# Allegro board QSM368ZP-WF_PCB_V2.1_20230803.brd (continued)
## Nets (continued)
100OHM_MIPI_DSI_TX1_D1N_1: D0512.4 J0501.24(MIPI_TDN1) R0571.2
100OHM_MIPI_DSI_TX1_D1P: D0512.1 R0570.1 U1301.34(DSI1_LN1_P)
100OHM_MIPI_DSI_TX1_D1P_1: D0512.3 J0501.23(MIPI_TDP1) R0570.2
100OHM_MIPI_DSI_TX1_D2N: D0511.2 R0569.1 U1301.28(DSI1_LN2_N)
100OHM_MIPI_DSI_TX1_D2N_1: D0511.4 J0501.21(MIPI_TDN2) R0569.2
100OHM_MIPI_DSI_TX1_D2P: D0511.1 R0568.1 U1301.24(DSI1_LN2_P)
100OHM_MIPI_DSI_TX1_D2P_1: D0511.3 J0501.20(MIPI_TDP2) R0568.2
100OHM_MIPI_DSI_TX1_D3N: D0514.2 R0567.1 U1301.23(DSI1_LN3_N)
100OHM_MIPI_DSI_TX1_D3N_1: D0514.4 J0501.18(MIPI_TDN3) R0567.2
100OHM_MIPI_DSI_TX1_D3P: D0514.1 R0566.1 U1301.19(DSI1_LN3_P)
100OHM_MIPI_DSI_TX1_D3P_1: D0514.3 J0501.17(MIPI_TDP3) R0566.2
CAM0_AVDD: B0201.2 J0201.16
CAM0_DOVDD_1V8: B0205.2 J0201.17
CAM0_PDN_L_GPIO3_D5: J0201.24 U1301.316(CAM0_PWDN)
CAM0_RST_L_GPIO3_D4: J0201.14 U1301.317(CAM0_RST)
CAM1_AVDD: B0204.2 J0202.16
CAM1_DOVDD_1V8: B0206.2 J0202.17
CAM1_MCLK: R0226.1 U1301.75(CAM1_MCLK)
CAM1_PDN_L_GPIO3_D3: J0202.24 U1301.313(CAM1_PWDN)
CAM1_RST_L_GPIO3_D2: J0202.14 U1301.314(CAM1_RST)
CAM_DOVDD_1V8: B0205.1 B0206.1 C0209.2 C0299.1 R0207.2 R0208.2 R0212.2 R0221.2 R0222.2 U0205.5(OUT)
CEC_HDMI: D0404.3(D) D0408.1 J0401.13(CEC) R0416.1
CMA0_MCLK: J0201.25 U1301.279(CAM0_MCLK)
DBG_RXD: D1256.2 J1201.23 U1301.378(DBG_RXD)
DBG_TXD: D1255.2 J1201.21 U1301.374(DBG_TXD)
DC12V: C0102.2 C0103.2 C0108.2 C0110.2 C0112.2 C0115.2 C0116.2 C0118.2 C0121.2 C0122.2 C0127.2 C0128.2 C0516.2 C0520.2 C0614.2 C0622.2 C0624.2 C0704.2 C0709.2 C0717.2 C1003.2 C1013.2 C1018.2 C1055.2 C1056.2 D0101.1 F0101.2 Q0502.2(S) R0104.2 R0106.2 R0113.2 R0116.1 R0117.2 R0503.1 R0509.1 R0620.2 R0723.2 TP0102.1 U0101.1(IN) U0103.1(IN) U0104.1(IN) U0604.1(IN) U0701.1(IN) U1001.16(PVCC)
EDP_BL_EN: D0505.3(C) J0502.10 R0522.1
EDP_DET: R0516.2 R0527.2 U1301.70(EDP_DET)
EDP_HPD: J0502.11 R0527.1
EDP_PWM: D0501.3(C) J0502.8 R0506.1
EDP_VDDIN: C0518.1 C0523.1 J0502.1 J0502.2 J0502.3 Q0501.3(D) R0506.2 R0522.2 R0525.2
EDP_VLED: C0506.2 C0522.2 J0502.28 Q0502.3(D) R0509.2
ETH1_REFCLKO_25M_M1: R0925.2 U1301.288(RGMII1_REFCLKOUT)
ETH_3V3_A: B0901.2 C0902.2 C0917.2 R0915.2 R0954.2
EXT_EN: R0166.2 R0526.2 R0644.2 U1301.217(EXT_EN)
FSPI_CS0N/FLASH_CS0N: R1125.2 U1301.281(GPIO1_D3)
FSPI_D0/FLASH_RDY: D0505.1(B) U1301.267(GPIO1_D1)
GMAC1_MDC_M1: R0931.2 U1301.290(RGMII1_MDC)
GMAC1_MDIO_M1: R0949.2 U1301.286(RGMII1_MDIO)
GPIO1_D4: R0709.1 R0721.1 U1301.277(GPIO1_D4)
GPIO3_A4: D0703.1(B) J1201.10 U1301.352(GPIO3_A4)
GPIO3_A7: J1201.12 U1301.347(GPIO3_A7)
GPIO3_D0: D0701.1(B) U1301.318(GPIO3_D0)
GPIO3_D1: D0503.1(B) D0507.1(B) U1301.319(GPIO3_D1)
GPIO4_B2: D0902.3(C) R0935.1 R0941.2 U1301.291(GPIO4_B2)
GPIO4_C2: R0726.1 U1301.376(I2S3_MCLK)
HDMI14_TX_PWREN_H_GPIO0_D5: Q0402.1(B) U1301.80(GPIO0_D5)
HDMI_5V: C0413.2 D0403.1 J0401.18(VCC5V) R0408.2
HDMI_TX_HPD_PORT: D0410.1 J0401.19(DETECT) R0401.1 R0425.1
HDMI_TX_HPDIN: R0401.2 U1301.379(HDMI_DET)
HDMITX_CEC_M0: D0404.2(S) R0428.1 U1301.382(HDMI_CEC)
HDMITX_SCL: R0405.1 U0413.2(S) U1301.387(HDMI_I2C_SCL)
HDMITX_SCL_M: D0407.1 J0401.15(SCL) R0426.1 U0413.3(D)
HDMITX_SDA: R0417.1 U0405.2(S) U1301.385(HDMI_I2C_SDA)
HDMITX_SDA_M: D0406.1 J0401.16(SDA) R0420.1 U0405.3(D)
HP_SNS: R1018.1 U1301.101(HPH_GND)
HPL_OUT: C1017.1 R1004.2 R1023.1 U1301.100(HPH_L)
HPR_OUT: C1016.1 R1010.1 R1024.2 U1301.102(HPH_R)
I2C1_SCL_TP: D0504.2 J0503.2(SCL) J1201.17 R0517.1 U1301.45(TP_I2C1_SCL)
I2C1_SDA_TP: D0509.2 J0503.1(SDA) J1201.19 R0508.1 U1301.40(TP_I2C1_SDA)
I2C2_SCL_M1: J0201.13 R0207.1 U1301.287(I2C2_SCL)
I2C2_SDA_M1: J0201.12 R0221.1 U1301.284(I2C2_SDA)
I2C3_SCL_M0: J0202.13 J1201.13 R0208.1 U1301.273(I2C3_SCL)
I2C3_SDA_M0: J0202.12 J1201.11 R0222.1 U1301.268(I2C3_SDA)
I2C4_SCL_M1: R0430.2 R1206.1 U0410.2(S) U1204.2(SCL) U1301.159(I2C4_SCL)
I2C4_SDA_M1: R0424.2 R1203.1 U0407.2(S) U1204.3(SDA) U1301.155(I2C4_SDA)
I2S3_LRCKM1: R0714.1 U1301.388(I2S3_LRCK)
I2S3_SCLKM1: R0724.1 U1301.386(I2S3_SCLK)
I2S3_SDIM1: R0703.1 U1301.383(I2S3_DIN)
I2S3_SDOM1: R0710.1 U1301.380(I2S3_DOUT)
INTB_A: D0902.1(B) R0935.2 R0953.2 U0902.31(INT_N/PME_N)
LAN0_D2_REC1_A: R0911.2 U0901.24
LAN0_D2_REC2_A: R0918.2 U0901.21
LAN0_D7_REC1_A: R0924.2 U0901.15
LAN0_D7_REC2_A: R0943.2 U0901.18
LCD0_BL_PWM4: R0422.2 U0409.5(CTRL) U1301.55(PWM4)
LCD1_BL_PWM5: R0512.2 U0504.5(CTRL) U1301.25(GPIO0_C4)
LCD_RST_L_GPIO3_C7: J0501.6(RESET) U1301.322(LCD1_RST)
LCDC_D0: R0203.2 U0202.3(EN) U1301.366(PCIE1_CLKREQ_N)
LCDC_D1: R0504.1 R0507.2 U0502.3(EN) U1301.367(PCIE1_WAKE_N)
LCDC_D9: R0204.2 U0204.5(EN) U1301.359(GPIO3_A2)
LCDC_D10: R0223.2 U0203.3(EN) U1301.354(GPIO3_A3)
LCDC_D12: R0228.1 U0205.3(EN) U1301.351(GPIO3_A5)
LCDC_D13: C1024.2 R1014.1 R1017.1 U1301.346(GPIO3_A6)
LCDC_D15: D0905.1(B) R0948.2 U1301.348(GPIO3_B0)
LCDC_D19: R1015.2 R1022.1 U1001.9(CTRL) U1301.342(GPIO3_B4)
LCDC_D21: Q0403.1(B) R0406.2 U1301.337(GPIO3_B6)
LCDC_HSYNC: R0319.1 U1301.333(PCIE1_RST_N)
LCM_LED+: J0501.1(LEDA) R0523.1
LCM_LED-: J0501.3(LEDK) R0530.2 U0504.1(FB)
LCMIO_1V8: C0519.2 J0501.13(VIO18) R0511.2 R0513.1
LED0/PHYAD0_A: R0929.1 R0956.2 U0902.32(LED0/CFG_EXT)
LED1/CFG_LDO0_A: R0901.1 R0907.2 R0933.1 R0939.1 U0902.33(LED1/CFG_LDO0)
LED2/CFG_LDO1_A: R0904.2 R0914.1 R0930.1 R0951.1 U0902.34(LED2/CFG_LDO1)
LVDS_CTP28: B0501.2 C0403.1 J0402.5 R0404.2 R0414.2 R0415.2 R0429.2
LVDS_LEDA: J0403.39 J0403.40 R0402.1
LVDS_LEDK: J0403.31 J0403.32 R0413.2 U0409.1(FB)
LVDS_RESET: C0404.1 J0403.5 Q0403.3(C) R0406.1 R0421.1
LVDS_TP_INT: J0402.3 Q0405.3(D) R0404.1 R0409.1
LVDS_TP_RST: C0406.1 J0402.6 Q0404.3(C) R0418.1 R0429.1
LVDS_TP_SCL: J0402.1 R0414.1 R0430.1 U0410.3(D)
LVDS_TP_SDA: J0402.2 R0415.1 R0424.1 U0407.3(D)
LVDS_VDD3V3: C0407.1 J0403.2 J0403.3 Q0401.3(D) R0421.2 R0427.1
MIC1_INN: R1099.2 U1301.97(MIC_M)
MIC1_INP: C1010.2 R1003.2 U1301.98(MIC_P)
MINI-PCIE-C_DTR: R0709.2 R0715.2
MINI-PCIE-C_RESET: R0706.1 R0711.2
MINI-PCIE-C_RXD: R0701.1 R0702.2
MINI-PCIE-C_TXD: R0707.2 R0732.1
MINI-PCIE-C_VDD_EXT: R0719.1 R0866.1
MINI-PCIE_DTR: R0704.1 R0733.2
MINI-PCIE_LED_WWAN#: D0706.1 J0701.42
MINI-PCIE_RXD: J0701.11 R0719.2 R0731.2
MINI-PCIE_TXD: J0701.13 R0729.2
MINI-PCIE_W_DISABLE#: C0701.2 D0701.3(C) J0701.20
MINI-PCIE_W_RESET#: J0701.22 R0716.2
MIPI_CTP28: B0502.2 C0533.1 J0503.6(VDD)
MODULE_4G_3V5: C0703.1 C0705.1 C0707.2 C0708.2 C0710.1 C0711.2 C0712.2 C0713.2 C0715.2 J0701.2 J0701.39 J0701.41 J0701.52 L0701.2 R0708.1 R0717.2 R0728.2 R0730.1 U0702.14(VCCB)
PDM_CLK1_M0_ADC: J1201.14 U1301.258(PDM_CLK1)
PDM_SDI1_M0_ADC: J1201.16 Q0405.2(S) R0403.1 R0409.2 U1301.253(PDM_DIN1)
PDM_SDI2_M0_ADC: J1201.18 Q0404.1(B) R0418.2 U1301.248(PDM_DIN2)
PDM_SDI3_M0_ADC: J1201.20 U1301.243(PDM_DIN3)
PHY_CLK125_A: R0934.1 U0902.35(CLKOUT)
PHYRSTB_A: C0903.1 D0905.3(C) R0942.2 R0948.1 U0902.12(RESET_N)
REGOUT_A: L0901.1 R0988.2 U0902.30(REG_O/LDO_O/NC)
RS232_RXD: J1201.4 U1103.7(T_OUT1)
RS232_TXD: J1201.2 U1103.8(R_IN1)
RS485_A: D1106.1 J1201.8 R1113.2 R1123.2 U1101.6(A)
RS485_B: D1104.1 J1201.6 R1123.1 R1129.2 U1101.7(B)
RTCIC_32KOUT: R1207.1 U1204.4(FOUT)
RTCIC_INT_L_GPIO0_D3: R1204.1 U1204.6(/IRQ) U1301.125(GPIO0_D3)
SARADC_VIN4: J1201.3 U1301.233(ADC4)
SARADC_VIN5: J1201.9 U1301.228(ADC5)
SARADC_VIN6: J1201.5 U1301.223(ADC6)
SARADC_VIN7: J1201.7 R0528.2 U1301.213(ADC7)
SDMMC0_DET_L: R0807.1 R0809.2 U1301.261(SD_DET)
SDMMC0_DET_L1: D0808.1 J0801.CD(CARD DETECION) R0807.2
SG368Z_PWRKEY: R1208.1 TP1203.1 U1301.226(PWRKEY)
SPK_OUT_LN: B1003.1 C1006.2 J1001.4
SPK_OUT_LP: B1005.1 C1009.1 J1001.3
SPK_OUT_RN: B1004.1 C1025.1 J1001.1
SPK_OUT_RP: B1001.1 C1023.2 J1001.2
SPKN_OUT: D1051.1 J1001.6 U1301.103(SPK_M)
SPKP_OUT: D1050.1 J1001.5 U1301.104(SPK_P)
TP_INT_L_GPIO0_B5: D0510.2 J0503.4(INT) U1301.35(TP_INT)
TP_RST_L_GPIO0_B6: D0513.2 J0503.3(RESET) U1301.30(TP_RST)
UART4_RX_3.3V: J1101.2 R1160.2
UART4_RXD: R1126.1 U1301.349(UART4_RXD)
UART4_RXD_3.3V: R1105.1 R1159.1
UART4_TX_3.3V: J1101.4 R1162.2
UART4_TXD: R1115.2 U1301.344(UART4_TXD)
UART4_TXD_3.3V: R1111.1 R1117.1 R1161.1
UART5_RX_3.3V: J1101.1 R1156.2
UART5_RXD: R1130.1 U1301.331(UART5_RXD)
UART5_RXD_3.3V: R1133.2 R1155.1
UART5_TX_3.3V: J1101.3 R1158.2
UART5_TXD: R1119.1 U1301.332(UART5_TXD)
UART5_TXD_3.3V: R1120.2 R1157.1
UART7_RXD: R0707.1 R0720.1 U1301.328(UART7_RXD)
UART7_TXD: R0702.1 R0713.1 U1301.327(UART7_TXD)
UART8_RXD: J1201.22 U1301.357(UART8_RXD)
UART8_TXD: J1201.24 U1301.361(UART8_TXD)
USB3_OTG0_ID: R0325.2 S0301.2(C) U1301.118(USB0_ID)
USB3_OTG0_VBUSDET: R0302.2 R0312.2 U1301.111(USB0_VBUS)
USB_HOST_PWREN_H_GPIO0_A6: R0602.2 R0607.2 R0612.2 R0618.2 R0623.2 R0624.2 U0601.4(EN/E\N\) U0602.4(EN/E\N\) U0603.4(EN/E\N\) U1301.85(HOST_PWR_EN)
USB_VBUS: C0301.2 C0303.2 C0352.1 C0353.1 C0354.1 C0355.1 D0354.1 D0355.1 J0301.1(VBUS1) J0302.1(VBUS) R0302.1 R0366.2 TP0303.1 U0304.1(OUT)
V_RTC: BAT1201.1 C1201.2 R1301.2 U1204.10(VBAT)
V_UP/BOOT: D1202.1 S1201.2(C) TP1201.1 U1301.236(VOL_UP/BOOT)
VDC_3V3: B0901.1 C0109.2 C0124.2 C0126.2 C0402.2 C0405.2 C0409.1 C0517.2 C0521.1 C1101.2 C1102.1 C1106.2 C1110.2 D0401.2 L0101.2 L0401.1 Q0401.2(S) Q0501.2(S) R0105.1 R0407.1 R0427.2 R0505.1 R0525.1 R0529.1 R1103.2 R1113.1 R1207.2 R1210.1 TP0103.1 U0409.6(VIN) U1101.8(VCC) U1102.A2(VREF_B) U1103.16(VCC)
VDC_5V: B0101.1 C0104.2 C0105.2 C0106.2 C0401.2 C0410.2 D0402.2 D0403.2 L0102.2 R0102.1 R0408.1 TP0101.1
XTAL1A: C0921.2 R0936.2 U0902.36(XTAL_I/ XTAL_O) X0901.1(X1)
XTAL2A: C0912.2 R0925.1 R0936.1 U0902.37(XTAL_O/ XTAL_I) X0901.3(X2)
N15679654: C0919.1 U0901.1
N15679880: C0986.1 U0901.10
N15679892: C0987.1 U0901.7
N15679900: C0988.1 U0901.4
N15680148: J0901.10(G+) R0908.1 R0939.2
N15680216: C0909.2 R0911.1 R0918.1 R0924.1 R0943.1
N15680388: D0901.1 J0901.9(G-) R0922.1 R0933.2
N15680410: J0901.12(Y+) R0938.2 R0951.2
N15680444: D0903.1 J0901.11(Y-) R0927.2 R0930.2
N16421517: D0706.2 R0730.2
N16421911: D0705.2 R0708.2
N16451445: R0610.2 R0622.2 U0602.3(F\L\G\)
N16756675: R0604.2 R0617.2 U0601.3(F\L\G\)
N16757889: R0603.2 R0614.2 U0603.3(F\L\G\)
N16762456: R0305.2 R0309.2 R0319.2 U0304.4(EN/E\N\)
N16762522: R0308.2 R0313.2 U0304.3(F\L\G\)
N16784705: C0806.2 D0803.3 J0802.C2(RST) R0803.2
N16784727: C0802.2 D0803.4 J0802.C3(CLK) R0810.2
N16784743: C0804.2 D0803.5 J0802.C7(I/O) R0804.1 R0808.2
N16788349: C0803.2 C0805.2 D0806.1 J0801.P4(VDD) R0813.2
N16817948: B1002.2 C1014.1 U1002.1(VDD)
N16818791: D1001.1 J1002.2(L AUDIO) R1023.2
N16820129: B1005.2 C1027.1 R1020.1 U1001.5(OUTPL)
N16820177: B1003.2 C1022.1 R1016.1 U1001.8(OUTNL)
N16820236: C1027.2 U1001.6(BSPL)
N16820242: C1022.2 U1001.7(BSNL)
N16820310: C1021.2 R1005.1 U1001.15(INPR)
N16820326: R1021.1 U1001.14(INNR)
N16820338: C1001.2 R1011.2 U1001.13(GVDD)
N16820356: C1008.1 R1007.2 R1011.1 U1001.12(PLIMIT)
N16820452: C1005.2 R1012.2 U1001.10(INPL)
N16820458: R1008.1 U1001.11(INNL)
N16820536: B1004.2 C1026.1 R1019.1 U1001.1(OUTNR)
N16820548: C1004.1 R1019.2
N16820558: B1001.2 C1020.1 R1002.1 U1001.4(OUTPR)
N16820570: C1012.1 R1002.2
N16820612: C1011.1 R1020.2
N16820614: C1007.1 R1016.2
N16820628: C1017.2 R1008.2
N16820646: C1016.2 R1021.2
N16820759: C1026.2 U1001.2(BSNR)
N16820857: C1020.2 U1001.3(BSPR)
N16829674: C1111.1 U1103.2(V+)
N16829682: C1104.2 U1103.6(V-)
N16829803: R1120.1 U1103.10(T_IN1)
N16830150: R1111.2 R1134.2 U1101.4(DI)
N16830180: R1105.2 U1101.1(RO)
N16830190: Q1101.3(C) Q1102.3(C) R1103.1 U1101.2(R\E\) U1101.3(DE)
N16831384: B0202.1 B0203.1 C0208.2 C0211.2 L0201.2 R0214.1 U0204.6(OUT)
N16831443: B0201.1 B0204.1 C0212.2 U0203.5(OUT)
N16831459: C0216.2 U0203.4(BP/FB)
N16831535: C0217.2 R0209.1 R0229.1 U0202.5(OUT)
N16831549: C0207.2 U0202.4(BP/FB)
N16832505: C0299.2 R0212.1 R0219.2 U0205.4(BP/FB)
N16833633: F0101.1 J0101.1 R0106.1
N16851360: B0501.1 B0502.1 C0526.2 U0501.5(OUT)
N16851388: R0510.1 R0518.2 R0526.1 U0501.3(EN)
N16851406: C0511.1 U0501.4(BP/FB)
N16851801: C0504.1 C0527.1 D0508.1 R0523.2
N16851821: D0508.2 L0501.2 U0504.4(SW)
N16865312: R0947.2 R0949.1 U0902.14(MDIO)
N16865348: R0931.1 U0902.13(MDC)
N16871216: R0913.1 U0902.39(RBIAS)
N16979946: R1107.1 R1132.1 U1102.C2(EN)
N16980060: R1115.1 U1102.D3(A4)
N16980062: R1130.2 U1102.A3(A1)
N16980064: R1126.2 U1102.C3(A3)
N16980078: R1119.2 U1102.B3(A2)
N17169242: J0202.25 R0226.2 R0227.1
N17248848: B0503.1 C0524.2 C0528.1 U0502.5(OUT)
N17248866: C0514.1 U0502.4(BP/FB)
N17269506: C0525.2 R0515.1 U0503.3(EN)
N17270599: C0535.2 R0513.2 U0503.1(VOUT)
N17274420: J0501.7(LCD_ID) R0528.1
N17308117: D1201.2 R1208.2 S1202.2
N17310824: D0102.2 R0116.2
N17312479: R0101.1 R0104.1 U0101.5(EN)
N17312557: C0111.2 U0101.4(BST)
N17312561: C0111.1 L0103.1 U0101.2(SW)
N17312853: R0108.2 R0115.2 U0101.6(FB)
N17316601: R0103.2 R0113.1 R0166.1 U0103.5(EN)
N17316611: C0113.2 U0103.4(BST)
N17316621: C0113.1 L0101.1 U0103.2(SW)
N17316661: R0105.2 R0114.1 U0103.6(FB)
N17321443: R0110.2 R0117.1 U0104.5(EN)
N17321453: C0114.2 U0104.4(BST)
N17321455: C0114.1 L0102.1 U0104.2(SW)
N17321503: R0102.2 R0112.1 U0104.6(FB)
N17391886: R0615.2 R0620.1 R0644.1 U0604.5(EN)
N17391896: C0618.2 U0604.4(BST)
N17391898: C0618.1 L0601.1 U0604.2(SW)
N17391938: R0606.2 R0613.1 U0604.6(FB)
N17593444: C1203.2 R1202.2 R1205.2 U1204.1(VIO)
N17594281: C1204.2 U1204.9(VOUT)
N17594510: C1202.2 R1210.2 R1211.2 U1204.8(VDD)
N17654307: J0501.5(LPTE) TP0502.1
N17980948: R0723.1 R0725.2 R0726.2 U0701.5(EN)
N17980958: C0714.2 U0701.4(BST)
N17980968: C0714.1 L0701.1 U0701.2(SW)
N17981000: R0717.1 R0718.2 U0701.6(FB)
N18035182: C0907.1 C0916.2 L0901.2 R0910.2 R0923.2 R0988.1
N18073365: D1003.1 J1002.3(R AUDIO) R1010.2
N18075719: D1004.1 J1002.4(DETECT1) R1014.2
N18080454: C1015.2 C1099.2 D1002.1 R1003.1 U1002.4(OUTPUT)
N18191565: Q1101.1(B) R1117.2 R1121.2
N18198024: Q1102.1(B) R1125.1
N18247329: D0402.1 R0420.2 R0426.2
N18365015: C0408.1 C0412.1 D0405.1 R0402.2
N18365073: D0405.2 L0401.2 U0409.4(SW)
N18366438: C0405.1 Q0401.1(G) Q0402.3(C) R0407.2
N18378711: C0517.1 D0507.3(C) Q0501.1(G) R0529.2
N18380308: C0516.1 D0503.3(C) Q0502.1(G) R0503.2
N18382144: J0502.9 TP0503.1
N18382149: J0502.30 TP0501.1
N18582530: R1301.1 U1301.171(VRTC)
N18603622: TP1401.1 U1301.231(RESET_N)
N18618933: D0401.1 R0416.2
N18646162: TP1403.1 U1301.232(VOL_DOWN)
N18646180: TP1404.1 U1301.227(ESC)
N18646198: TP1405.1 U1301.222(MENU)
N18646284: R1457.2 TP1402.1 U1301.221(PON_1)
N18670938: L0201.1 U0204.4(SW)
N18671521: C0211.1 R0214.2 R0224.2 U0204.1(FB)
N18920153: R1468.1 R1469.2 U1301.234(RESERVED17)
N18932423: R1455.1 R1456.2 R1457.1
N19051361: C1113.1 U1103.4(C2+)
N19051366: C1113.2 U1103.5(C2-)
N19051381: C1105.1 U1103.1(C1+)
N19051390: C1105.2 U1103.3(C1-)
N19051717: R1133.1 U1103.9(R_OUT1)
N19139644: D0353.1 J0302.4(USB_ID) R0325.1
N19156624: R1155.2 R1156.1 U1102.A1(B1)
N19156735: R1157.2 R1158.1 U1102.B1(B2)
N19156807: R1159.2 R1160.1 U1102.C1(B3)
N19156822: R1161.2 R1162.1 U1102.D1(B4)
N19197680: R1466.1 R1467.1 U1301.229(RESERVED15)
N19332658: J0701.17 TP0702.1
N19332747: J0701.1 TP0703.1
N19347845: R0731.1 U0702.13(B1)
N19347847: R0729.1 U0702.12(B2)
N19347865: R0705.1 R0727.2 U0702.8(OE)
N19347930: R0713.2 U0702.2(A1)
N19349212: R0720.2 U0702.3(A2)
N19352428: J0701.45 R0724.2
N19352448: J0701.47 R0703.2
N19352470: J0701.49 R0710.2
N19352490: J0701.51 R0714.2
N19352717: C0706.2 D0703.3(C) R0711.1 R0716.1
N19354367: J0701.23 R0701.2
N19354450: J0701.31 R0704.2 R0732.2
N19356842: J0701.33 R0706.2
N19357290: J0701.24 R0728.1
N19357904: J0701.32 TP0701.1
N19358667: R0721.2 U0702.4(A3)
N19358768: R0733.1 U0702.11(B3)
N19359275: J0701.46 R0715.1
N19367635: R0722.1 U0702.10(B4)
N193479154: R0712.2 U0702.5(A4)

Pads without a net: HOLE1201 1; HOLE1202 1; HOLE1203 1; HOLE1204 1; HOLE1205 1; HOLE1206 1; J0201 2 5 6 7; J0202 2 5 6 7; J0301 2 3; J0401 14; J0403 1 4 6 23 24 26 27 28 29 33 34 35 36 37 38; J0501 2 4 8 9 10 11 15; J0502 4 6 7 29; J0701 3 5 6 7 16 19 25 28 30 48; J0802 C4 C6 C8; J1002 6; LAB1201 1; S0301 1; S1201 1; U0409 2; U0504 2; U0702 6 9; U1103 11 12 13 14; U1204 5; U1301 10 15 20 49 50 53 54 58 59 60 63 64 68 69 73 81 82 86 87 90 91 123 130 134 135 140 150 160 163 164 165 168 169 170 172 173 174 175 177 178 179 181 182 183 185 192 197 198 201 204 205 208 209 210 214 215 218 219 220 225 230 239 240 242 244 245 249 250 254 255 260 264 265 269 270 271 272 275 276 299 315 320 321 329 330 334 335 336 339 340 343 345 358 360 362 363 364 365 368 369 377 381 384

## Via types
v1: diameter 0.5, hole 0.25, TOP to BOTTOM, 2768 vias

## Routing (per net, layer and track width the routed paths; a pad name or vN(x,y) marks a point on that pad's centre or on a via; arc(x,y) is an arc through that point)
AVDD10_A: length 23.7
  TOP w0.5: v1(109.08,50.73) 109.1,50.7 109.1,49.5 109.8,48.8 109.8,43.12 110.38,42.55 110.38,40.67 v1(109.8,40.1) 106.72,40.1 C0913.1 106.22,40.6 v1(105.67,40.6) C0910.1 v1(103.7,40.6)
  BOTTOM w0.2: U0902.8 103.67,40.62 v1(103.7,40.6) ; v1(109.8,40.1) 109.22,40.67 C0915.1 108.83,40.67 108.5,41 108.5,41.55 107.53,42.52 U0902.38 ; U0902.3 v1(105.67,40.6)
  BOTTOM w0.5: R0923.1 v1(109.08,50.73)
AVDD33_A: length 20.5
  TOP w0.3: C0904.1 102.1,41.23 v1(102.15,41.27) 102.4,41.52 107.58,41.52 v1(107.75,41.35)
  TOP w0.5: v1(96.17,40) 96.65,40 97,40.35 100.03,40.35 100.9,41.23 C0904.1
  BOTTOM w0.2: U0902.11 102.2,41.6 ; C0908.1 107.85,41.35 107.47,41.73 U0902.40
  BOTTOM w0.3: v1(102.15,41.27) 102.2,41.33 102.2,41.6 ; C0908.1 107.88,40.5 107.88,41.23 v1(107.75,41.35)
  BOTTOM w0.5: v1(96.17,40) 95.3,40 92.85,42.45 R0915.1
DVDD0_1V1: length 12.8
  TOP w0.3: v1(97.45,96.95) J0201.1
  BOTTOM w0.5: v1(97.45,96.95) C0201.1 C0210.1 97.38,95.25 97.38,93.5 96.67,92.8 90.4,92.8 90.08,93.12 B0202.2
DVDD1_1V1: length 3.8
  TOP w0.3: 86.78,97.75 86.78,97.17
  TOP w0.4: 86.78,97.17 v1(86.78,97)
  BOTTOM w0.5: B0203.2 C0214.1 C0202.1 86.38,96.6 v1(86.78,97)
DVDD3V3_A: length 93.8
  TOP w0.2: v1(111.65,46.75) 112.1,47.2 112.1,48.02 111.72,48.4 v1(111.72,50.1) ; R0938.1 103.78,18.52 103.78,20.12 104.8,21.15 104.8,22.07 105.2,22.48 107.08,22.48 109.47,24.88 v1(111.1,24.88) ; v1(109.58,18.95) R0908.2
  TOP w0.25: v1(111.72,50.1) 110.33,51.5 106.55,51.5 v1(106.53,51.48)
  TOP w0.5: v1(106.53,51.48) 106.53,51 107.33,50.2 107.33,44.02 106.42,43.12 102.58,43.12 R0942.1 101.67,43 99.62,40.95 96.72,40.95 96.45,40.67 v1(96.17,40.67)
  INNER LAYER 3 w0.2: v1(109.58,18.95) 111.1,20.48 v1(111.1,24.88) 116.47,30.25 116.47,41.95 117.33,42.8 117.33,48.48 v1(116.75,49.05)
  BOTTOM w0.2: U0902.29 106.08,46.7 ; v1(111.65,46.75) 111.47,46.75 R0904.1 ; v1(111.72,50.1) 112.03,50.4 R0953.1 R0956.1 R0907.1 116,49.55 116.5,49.05 v1(116.75,49.05)
  BOTTOM w0.5: v1(96.17,40.67) 95.47,40.67 93.12,43.02 R0954.1 R0950.2 ; v1(106.53,51.48) 106.21,51.16 C0911.2 106.2,50.44 C0906.1 C0922.1 106.2,46.8
DVDD10_A: length 34
  TOP w0.5: v1(92.72,52.83) 93.15,53.25 99.28,53.25 100.08,54.05 105.95,54.05 106.97,53.02 v1(107.15,53.02)
  BOTTOM w0.5: 102.65,46.42 102.22,46.85 C0905.1 100.03,46.85 99.6,46.42 95.12,46.42 94.62,46.92 92.92,46.92 90.95,48.9 90.95,51.55 92.22,52.83 v1(92.72,52.83) ; R0910.1 v1(107.15,53.02)
DVDDRG_A: length 46.9
  BOTTOM w0.1: R0947.1 96.62,41.06 96.59,41.06 96.5,41.15 95.58,41.15 94.25,42.48 94.25,44.75 94.03,44.98 92.22,44.98
  BOTTOM w0.2: U0902.28 105.67,47.33
  BOTTOM w0.3: R0928.1 R0921.1 96.9,52.95 ; 100.3,52.95 R0905.1 R0919.1 ; 93.5,53.23 R0912.1 R0909.1
  BOTTOM w0.4: 104.45,49.59 104.45,48.55 105.53,47.48 ; 104.45,49.59 C0918.2 ; 104.45,49.59 C0914.1 104.45,51.1 102.6,52.95 96.9,52.95 96.62,53.23 93.5,53.23 93.3,53.42 91.47,53.42 89.33,51.27 89.33,46.63 90.85,45.1 92.1,45.1 92.22,44.98
  BOTTOM w0.5: R0950.1 92.22,44.98
GND: length 4581.4
  TOP w0.1: 92.38,38.02 91.92,38.02 90.88,36.98 83.9,36.98 83.67,36.75 J0701.4 83.65,35.77 ; 92.38,38.02 92.47,37.92 J0701.18 92.47,34.85 92.95,34.38 93.25,34.38 v1(93.47,34.15) ; 92.38,38.02 93.78,38.02 94.03,38.27 ; 8,25.57 8.62,26.2 8.62,78.05 10.53,79.95 31.77,79.95 33.95,77.78 36.73,77.78 37.2,78.25 43.45,78.25 44.6,77.1 44.6,74.65 ; 99.43,85.38 v1(97.42,85.38) 96.78,85.38 96.06,84.66 ; 99.43,85.38 100.33,85.38 102.7,83 111.08,83 111.12,82.95 ; 99.43,85.38 103.65,81.15 109.33,81.15 111.12,82.95 ; 89.3,82.8 89.25,82.75 89.25,76.75 84.98,72.47 80.58,72.47 ; U0201.6 v1(78.75,92.22) ; 111.12,82.95 v1(112.15,82.95) ; v1(73.53,46.5) 73.78,46.75 87.58,46.75 90.5,49.67 90.5,52.1 92.9,54.5 98.83,54.5 99.5,55.17 106.47,55.17 107.4,54.25 108.15,54.25 112.85,49.55 112.85,47.77 v1(112.67,47.6) ; 84.58,38.45 90.1,38.45 94.12,42.48 95.4,42.48 95.83,42.9 v1(96.1,42.9) ; v1(71.17,75.62) 71.78,75.62 72.22,76.08 84.53,76.08 86.38,77.92 86.38,88.38 88.25,90.25 90.47,90.25 90.78,90.55 90.78,90.85 91.08,91.15 91.08,91.33 ; v1(65.2,19.85) 64.85,20.2 62.05,20.2 54.2,28.05 49.8,28.05 46.45,31.4 v1(46.45,31.82) ; v1(71.35,72.85) 71.72,72.85 73.5,74.62 85.12,74.62 87.95,77.45 87.95,86.42 90.2,88.67 96.05,88.67 96.8,89.42 97,89.42 97.65,90.08 v1(97.88,90.08) ; v1(87.28,19.7) 84.67,22.3 79.05,22.3 74.95,26.4 74.95,28.62 73.83,29.75 64.17,29.75 64.03,29.9 63.3,29.18 v1(63.3,29.07) 63.35,29.12 63.35,29.27 ; v1(67.83,73.42) 68.17,73.42 68.85,74.1 71.58,74.1 72.8,75.33 84.83,75.33 87.15,77.64 87.15,88.12 88.4,89.38 94.53,89.38 95.08,89.92 ; v1(89.92,83.5) 89.92,82.95 90.28,82.6 90.28,81.95 90.15,81.83 90.15,80.9 89.88,80.62 89.88,80.35 ; 103.97,24.1 104.08,24.1 104.28,23.9 106.67,23.9 107.08,24.3 ; 72.35,54.02 72.53,53.85 81.46,53.85 91.55,63.94 91.55,67.15 91.3,67.4 v1(91.3,67.42) 91.3,68.05 93.78,70.53 93.78,72.03 94,72.25 94,79.42 94.67,80.1 94.67,83.47 v1(94.9,83.7) ; 94.17,70.2 94.17,67.75 93.2,66.78 v1(93.2,66.03) 93.2,63.77 81.97,52.55 72.78,52.55 72.58,52.35 v1(72.58,52.05) 72.95,51.67 73.45,51.67 73.67,51.9 73.67,52 73.78,52.1 82.15,52.1 94.15,64.1 94.15,66.6 ; 94.17,70.2 94.35,70.38 94.35,71.8 94.95,72.4 94.95,83.08 95.9,84.03 v1(96.35,84.03) 96.45,83.92 96.45,83.28 95.44,82.26 95.44,72.24 94.78,71.58 94.78,64.13 82.32,51.67 74.08,51.67 73.65,51.25 71.33,51.25 70.97,50.9 v1(70.97,50.58) ; 94.17,70.2 91.97,68 91.97,63.75 81.65,53.42 72.38,53.42 72.17,53.23 70.83,53.23 v1(70.62,53.42) ; v1(113.08,45.17) 113.15,45.17 113.5,45.52 113.5,49.77 108.4,54.88 107.62,54.88 106.7,55.8 99.25,55.8 98.58,55.12 92.67,55.12 89.88,52.33 89.88,49.9 87.33,47.35 72.85,47.35 71.96,46.46 71.85,46.51 v1(71.78,46.48) 71.8,46.5 71.8,46.75 71.7,46.85 71.7,47.52 71.92,47.75 87.12,47.75 89.45,50.08 89.45,52.54 92.43,55.52 98.33,55.52 99.03,56.23 106.95,56.23 107.88,55.3 108.65,55.3 113.35,50.6 v1(113.58,50.6) ; U1401.1 v1(30.85,22.95) ; v1(100.53,44.88) 100.53,44.68 98.62,42.77 96.2,42.77 96.1,42.88 v1(96.1,42.9) ; v1(34.3,89.33) 34.08,89.55 19.65,89.55 19.48,89.38 v1(19.38,89.38) ; J0701.26 95.45,35.98 95.45,36.98 v1(95.58,37.1) ; 85.2,20.05 85.2,20.2 83.88,21.52 78.6,21.52 ; 67.22,32.2 75.08,32.2 81.95,39.08 89.88,39.08 93.92,43.12 94.6,43.12 95.08,43.6 95.62,43.6 96.14,43.08 96.14,42.94 v1(96.1,42.9) ; v1(71.58,47.45) 71.58,47.1 71.22,46.75 70.55,46.75 70.45,46.65 70.45,45.35 70.85,44.95 75.17,44.95 75.58,44.55 86.15,44.55 86.35,44.75 86.47,44.75 v1(86.95,45.23) 87.55,45.23 88.97,46.65 88.97,46.88 90.53,48.42 v1(90.58,48.42) ; v1(47.37,17.73) 47.37,18.23 D0356.2 ; v1(86.97,91.2) 85.66,89.88 85.66,78.25 84.17,76.76 76.79,76.76 75.38,78.17 72.4,78.17 71.97,78.6 71.78,78.6 ; J0701.9 85.67,26.35 85.5,26.18 v1(84.88,26.18) ; 65.47,34.02 65.92,33.58 65.92,32 66.75,31.18 75.22,31.18 81.6,37.55 90.38,37.55 91.8,38.98 v1(92.05,38.98) v1(93.1,40.02) 94.2,40.02 95.35,41.17 96.22,41.17 96.45,41.4 99.2,41.4 103.17,45.38 103.78,45.38 v1(104.03,45.12) ; v1(98.67,38.5) 98.67,38.85 99.08,39.25 101.22,39.25 101.35,39.12 101.35,37.3 ; v1(97.6,45.17) 97.4,45.38 93.5,45.38 89.05,40.92 81.2,40.92 75.1,34.83 74.8,34.83 v1(74.78,34.8) ; v1(97.6,45.17) 97.9,44.88 ; v1(97.6,45.17) 97.7,45.17 98.05,44.83 98.38,44.83 98.67,45.12 98.67,45.52 98.2,46 93.28,46 88.8,41.52 80.95,41.52 75.05,35.62 71.28,35.62 70.3,36.6 ; 42.77,74.75 42.8,74.78 42.8,76.97 42.23,77.55 37.6,77.55 ; v1(103.95,52.45) 103.95,52.73 103.03,53.65 100.25,53.65 99.45,52.85 98.6,52.85 98.05,52.3 v1(97.95,52.3) 97.92,52.27 97.47,52.27 v1(97.45,52.3) ; 34.74,20.46 40.4,26.12 52.77,26.12 57.08,21.82 v1(57.08,20) ; 116.3,35.2 116.65,34.85 S0301.5 ; v1(73.78,19.45) 73.5,19.73 73,19.73 70.67,22.05 62.8,22.05 54.88,29.98 50.5,29.98 49.1,31.38 49.1,31.68 v1(48.98,31.8) ; D0606.2 89.67,20.29 86.88,23.07 79.42,23.07 75.75,26.75 75.75,28.93 74.12,30.55 64.8,30.55 64.53,30.82 64.2,30.82 63.62,31.4 63.62,31.73 ; 69.33,34.67 69.45,34.67 70.55,33.58 74.7,33.58 81.45,40.33 89.33,40.33 93.58,44.58 v1(93.85,44.58) ; 93.3,53.67 99.08,53.67 99.85,54.45 106.15,54.45 107.12,53.48 107.33,53.48 107.62,53.17 107.62,52.23 107.53,52.12 106.42,52.12 v1(106.4,52.1) ; U0404.6 v1(7.28,16.45) U0404.5 ; v1(95.83,49.17) 95.97,49.17 96.33,48.83 96.33,48.08 96.03,47.77 92.4,47.77 92.22,47.6 92.22,46.67 88.35,42.8 80.47,42.8 77.72,40.05 74.55,36.88 71.8,36.88 70.35,38.33 70.25,38.33 v1(69.42,39.15) ; v1(72.6,34.65) 72.6,34.77 72.85,35.02 71.03,35.02 71,35 70.58,35.42 ; R1099.1 17.8,89.25 17.4,89.25 v1(17.2,89.45) ; 38.88,23.48 40.75,25.35 52.45,25.35 55.98,21.82 v1(55.98,19.43) ; 71.4,34.33 71.5,34.23 72.47,34.23 72.58,34.33 ; 86.2,74.65 88.65,77.1 88.62,77.12 88.62,85.8 88.65,85.83 ; 79.08,18.98 78.67,19.38 78.67,21.45 78.6,21.52 ; v1(99.17,47.02) 98.75,46.6 93.03,46.6 88.58,42.15 80.7,42.15 74.8,36.25 71.53,36.25 70.2,37.58 69.4,37.58 ; v1(29.27,72.45) 28.82,72 28.38,72 27.8,72.58 27.8,74.2 27.43,74.58 21.7,74.58 v1(21.57,74.7) 21.45,74.58 14.57,74.58 14.3,74.85 13.7,74.25 v1(13.53,74.25) ; 89.75,80.35 89.7,80.3 89.7,76.33 85.44,72.08 79.67,72.08 ; U1301.285 57.35,31 59.2,29.15 59.2,28.85 59.98,28.07 v1(60.8,28.07) ; 78.6,21.52 74.08,26.05 74.08,28.18 73.6,28.65 73.35,28.65 v1(73.35,28.62) ; R0507.1 v1(14.25,95.25) ; v1(44.65,31.5) 44.65,31.3 v1(48.23,27.73) 48.33,27.73 48.98,27.07 53.52,27.07 v1(55.33,25.27) ; 109.35,58.43 113.26,54.52 115.65,54.52 117.64,52.54 117.64,49.7 119.13,48.2 v1(119.25,48.2) ; 88.91,34.61 88.85,34.55 88.85,33.42 v1(88.99,33.29) ; v1(42.15,69.4) v1(42.15,70.05) ; 65.62,36.7 65.92,36.4 66,36.4 ; v1(90.72,47.92) 91.22,48.42 91.22,51.5 91.95,52.23 v1(92.75,52.23) ; v1(81.85,61.23) 81.85,60.88 80.2,59.23 75.1,59.23 69.83,53.95 69.83,53.25 69.38,52.8 69.38,51.7 69.12,51.45 67.58,51.45 66.95,52.08 65.65,52.08 65.45,52.27 ; v1(76.03,69.47) 76.1,69.4 ; D0801.2 69.62,17.27 69.62,19.93 68.75,20.8 62.3,20.8 54.38,28.73 49.98,28.73 47.48,31.23 v1(47.48,31.82) ; U0208.6 v1(82.47,92.25)
  TOP w0.3: U1301.143 27.75,55.98 ; U1301.143 27.1,55.48 ; U1301.143 27.75,54.97 ; U1301.143 28.4,55.48 ; 29,64.28 U1301.115 ; U1301.115 30.3,64.28 ; U1301.115 29.65,64.78 ; 67.7,45.88 U1301.326 ; U1301.326 68.35,45.37 ; U1301.326 68.35,46.38 ; U1301.326 69,45.88 ; U1301.196 25.35,33.53 ; U1301.196 25.35,32.22 ; U1301.196 24.85,32.88 ; U1301.196 25.85,32.88 ; 37.65,69.47 U1301.78 ; U1301.78 38.15,70.13 ; U1301.78 38.65,69.47 ; U1301.78 38.15,68.82 ; U1301.409 56.9,55.58 ; U1301.409 56.15,54.82 ; U1301.409 56.15,56.33 ; U1301.409 55.4,55.58 ; 16.95,2.25 J0401.22 ; J0401.22 18.13,3.92 ; J0401.22 15.77,3.92 ; 45.4,58.08 U1301.404 ; U1301.404 46.9,58.08 ; U1301.404 46.15,58.83 ; U1301.404 46.15,57.32 ; 46.45,71.38 U1301.52 ; U1301.52 47.45,71.38 ; U1301.52 46.95,70.72 ; U1301.52 46.95,72.03 ; 0.8,96.45 J0101.4 ; J0101.4 2.17,94.32 ; J0101.4 2.17,98.58 ; J0101.4 3.55,96.45 ; U1301.444 36.9,48.08 ; U1301.444 36.15,47.32 ; U1301.444 36.15,48.83 ; U1301.444 35.4,48.08 ; 50.4,58.08 U1301.402 ; U1301.402 51.15,58.83 ; U1301.402 51.15,57.32 ; U1301.402 51.9,58.08 ; 64.55,40.57 U1301.309 ; U1301.309 65.2,41.08 ; U1301.309 63.9,41.08 ; U1301.22 56.55,72.03 ; U1301.22 56.05,71.38 ; U1301.22 57.05,71.38 ; U1301.22 56.55,70.72 ; 32.05,67.58 U1301.93 ; U1301.93 32.55,66.92 ; U1301.93 33.05,67.58 ; J0301.19 45.39,14.7 ; J0301.19 43.47,16.62 ; J0301.19 41.54,14.7 ; 25.85,55.77 U1301.142 ; U1301.142 25.85,56.78 ; U1301.142 26.5,56.27 ; U1301.142 25.2,56.27 ; 42.45,40.48 U1301.235 ; U1301.235 42.95,41.13 ; U1301.235 42.95,39.82 ; U1301.235 43.45,40.48 ; U1301.434 39.4,50.58 ; U1301.434 38.65,49.82 ; U1301.434 38.65,51.33 ; U1301.434 37.9,50.58 ; 48.65,52.32 U1301.421 ; U1301.421 48.65,53.83 ; U1301.421 49.4,53.08 ; U1301.421 47.9,53.08 ; 29,53.08 U1301.149 ; U1301.149 29.65,53.58 ; U1301.149 30.3,53.08 ; U1301.149 29.65,52.57 ; U1301.410 54.4,55.58 ; U1301.410 52.9,55.58 ; U1301.410 53.65,54.82 ; U1301.410 53.65,56.33 ; U1301.191 25.85,39.18 ; U1301.191 26.5,38.67 ; U1301.191 25.85,38.17 ; U1301.191 25.2,38.67 ; 42.95,36.02 U1301.238 ; U1301.238 42.95,37.33 ; U1301.238 43.45,36.67 ; 35.4,60.58 U1301.399 ; U1301.399 36.9,60.58 ; U1301.399 36.15,61.33 ; U1301.399 36.15,59.82 ; U1301.263 51.45,36.67 ; U1301.263 50.95,36.02 ; U1301.263 50.95,37.33 ; U1301.263 50.45,36.67 ; J0101.5 13.45,96.45 ; J0101.5 10.7,96.45 ; J0101.5 12.07,94.32 ; J0101.5 12.07,98.58 ; 56.15,59.82 U1301.391 ; U1301.391 55.4,60.58 ; U1301.391 56.15,61.33 ; U1301.391 56.9,60.58 ; 31.25,69.47 U1301.96 ; U1301.96 32.25,69.47 ; U1301.96 v1(31.75,71.53) ; U1301.338 65.2,50.67 ; U1301.338 64.55,50.17 ; U1301.338 64.55,51.18 ; U1301.338 63.9,50.67 ; U1301.418 56.15,53.83 ; U1301.418 56.9,53.08 ; U1301.418 55.4,53.08 ; U1301.418 56.15,52.32 ; 2.45,7.85 J0401.20 ; J0401.20 3.63,9.93 ; J0401.20 1.27,9.93 ; J0401.20 2.45,12 ; U1301.430 49.4,50.58 ; U1301.430 48.65,51.33 ; U1301.430 48.65,49.82 ; U1301.430 47.9,50.58 ; J0301.22 58.53,14.7 ; J0301.22 54.68,14.7 ; J0301.22 56.6,12.77 ; J0301.22 56.6,16.62 ; U1301.373 65.2,61.88 ; U1301.373 64.55,62.38 ; U1301.373 63.9,61.88 ; U1301.373 64.55,61.37 ; U1301.95 33.05,71.38 ; U1301.95 32.05,71.38 ; U1301.95 32.55,72.03 ; U1301.95 32.55,70.72 ; J0301.7 50.86,12.52 ; J0301.7 50.03,11.69 ; J0301.7 50.03,13.34 ; J0301.7 49.21,12.52 ; 52.9,53.08 U1301.419 ; U1301.419 53.65,52.32 ; U1301.419 53.65,53.83 ; U1301.419 54.4,53.08 ; 38.45,71.38 U1301.77 ; U1301.77 38.95,72.03 ; U1301.77 38.95,70.72 ; U1301.77 39.45,71.38 ; U1301.119 30.3,62.67 ; U1301.119 29,62.67 ; U1301.119 29.65,62.17 ; U1301.116 23.95,65.58 ; U1301.116 24.6,65.08 ; U1301.116 23.3,65.08 ; 38.45,67.58 U1301.74 ; U1301.74 38.95,68.23 ; U1301.74 38.95,66.92 ; U1301.74 39.45,67.58 ; U1301.105 25.35,73.93 ; U1301.105 25.85,73.28 ; U1301.105 25.35,72.62 ; U1301.105 24.85,73.28 ; 66.95,32.22 U1301.300 67.45,32.88 ; 36.15,49.82 U1301.435 ; U1301.435 35.4,50.58 ; U1301.435 36.9,50.58 ; U1301.435 36.15,51.33 ; 52.71,14.21 J0301.13 54.36,14.21 ; 43.65,54.82 U1301.414 ; U1301.414 42.9,55.58 ; U1301.414 43.65,56.33 ; U1301.414 44.4,55.58 ; U1301.200 29.85,34.77 ; U1301.200 29.35,35.43 ; U1301.200 28.85,34.77 ; U1301.200 29.35,34.12 ; J1101.6 114.43,62.75 ; J1101.6 115.52,61.66 ; J1101.6 114.43,60.58 ; J1101.6 113.34,61.66 ; 66.95,72.62 U1301.1 ; U1301.1 66.95,73.93 ; U1301.1 67.45,73.28 ; U1301.437 53.65,48.83 ; U1301.437 52.9,48.08 ; U1301.437 54.4,48.08 ; U1301.437 53.65,47.32 ; 37.9,58.08 U1301.407 ; U1301.407 38.65,57.32 ; U1301.407 38.65,58.83 ; U1301.407 39.4,58.08 ; 51.15,59.82 U1301.393 ; U1301.393 51.9,60.58 ; U1301.393 51.15,61.33 ; U1301.393 50.4,60.58 ; 27.75,58.17 U1301.133 ; U1301.133 28.4,58.67 ; U1301.133 27.75,59.18 ; U1301.133 27.1,58.67 ; 34.45,32.88 U1301.216 ; U1301.216 34.95,32.22 ; U1301.216 34.95,33.53 ; U1301.216 35.45,32.88 ; 45.4,60.58 U1301.395 ; U1301.395 46.15,59.82 ; U1301.395 46.15,61.33 ; U1301.395 46.9,60.58 ; 27.75,56.57 U1301.138 ; U1301.138 28.4,57.08 ; U1301.138 27.1,57.08 ; U1301.138 27.75,57.58 ; 42.9,53.08 U1301.423 ; U1301.423 43.65,52.32 ; U1301.423 44.4,53.08 ; U1301.120 32.2,61.88 ; U1301.120 31.55,62.38 ; U1301.120 30.9,61.88 ; U1301.120 31.55,61.37 ; U1301.145 31.55,54.38 ; U1301.145 30.9,53.88 ; U1301.145 32.2,53.88 ; U1301.145 31.55,53.37 ; 47.75,72.62 U1301.51 ; U1301.51 47.75,73.93 ; U1301.51 47.25,73.28 ; 51.15,52.32 U1301.420 ; U1301.420 51.15,53.83 ; U1301.420 50.4,53.08 ; U1301.420 51.9,53.08 ; U1301.76 39.75,73.93 ; U1301.76 39.25,73.28 ; U1301.76 39.75,72.62 ; U1301.350 61.4,55.48 ; U1301.350 60.75,55.98 ; U1301.350 60.75,54.97 ; U1301.350 60.1,55.48 ; U1301.186 28.4,41.08 ; U1301.186 27.1,41.08 ; U1301.186 27.75,40.57 ; U1301.186 27.75,41.58 ; J0601.1 84.2,15.68 ; J0601.1 83.33,13.65 ; J0601.1 82.45,15.68 ; J0601.1 83.33,17.7 ; U1301.431 46.15,51.33 ; U1301.431 46.9,50.58 ; U1301.431 46.15,49.82 ; U1301.431 45.4,50.58 ; U1202.1 19.15,43.25 ; U1202.1 19.15,36.9 ; U1202.1 22.33,40.08 ; U1202.1 15.97,40.08 ; U1301.416 39.4,55.58 ; U1301.416 37.9,55.58 ; U1301.416 38.65,56.33 ; U1301.416 38.65,54.82 ; 83.33,7.97 J0601.2 ; J0601.2 82.45,9.99 ; J0601.2 84.2,9.99 ; J0601.2 83.33,12.02 ; U1301.438 51.9,48.08 ; U1301.438 50.4,48.08 ; U1301.438 51.15,48.83 ; U1301.438 51.15,47.32 ; 49.65,38.58 U1301.259 ; U1301.259 50.65,38.58 ; U1301.259 50.15,39.23 ; U1301.259 50.15,37.92 ; 51.15,49.82 U1301.429 ; U1301.429 51.15,51.33 ; U1301.429 51.9,50.58 ; U1301.429 50.4,50.58 ; 40.4,58.08 U1301.406 ; U1301.406 41.15,58.83 ; U1301.406 41.15,57.32 ; U1301.406 41.9,58.08 ; U1301.453 36.9,45.58 ; U1301.453 36.15,46.33 ; U1301.453 36.15,44.82 ; U1301.453 35.4,45.58 ; U1301.390 69,71.47 ; U1301.390 68.35,71.98 ; U1301.390 67.7,71.47 ; U1301.158 27.75,51.18 ; U1301.158 27.75,50.17 ; U1301.158 28.4,50.67 ; U1301.158 27.1,50.67 ; U1301.144 29.65,55.18 ; U1301.144 29.65,54.17 ; U1301.144 30.3,54.67 ; U1301.144 29,54.67 ; 25.2,49.88 U1301.162 ; U1301.162 25.85,50.38 ; U1301.162 25.85,49.37 ; U1301.162 26.5,49.88 ; 50.4,55.58 U1301.411 ; U1301.411 51.15,54.82 ; U1301.411 51.15,56.33 ; U1301.411 51.9,55.58 ; 69.97,66.08 U1203.1 ; U1203.1 73.15,69.25 ; U1203.1 76.33,66.08 ; U1203.1 73.15,62.9 ; U1301.324 63.3,46.67 ; U1301.324 62,46.67 ; U1301.324 62.65,47.18 ; U1301.324 62.65,46.17 ; U1301.433 41.15,51.33 ; U1301.433 40.4,50.58 ; U1301.433 41.9,50.58 ; U1301.433 41.15,49.82 ; 45.4,53.08 U1301.422 ; U1301.422 46.15,52.32 ; U1301.422 46.9,53.08 ; U1301.422 46.15,53.83 ; 55.4,45.58 U1301.445 ; U1301.445 56.9,45.58 ; U1301.445 56.15,46.33 ; U1301.445 56.15,44.82 ; U1301.398 38.65,61.33 ; U1301.398 39.4,60.58 ; U1301.398 38.65,59.82 ; U1301.398 37.9,60.58 ; U1301.325 60.75,47.98 ; U1301.325 60.75,46.97 ; U1301.325 61.4,47.48 ; U1301.325 60.1,47.48 ; J1101.5 116.97,62.75 ; J1101.5 118.06,61.66 ; J1101.5 115.88,61.66 ; J1101.5 116.97,60.58 ; U1301.184 23.95,43.18 ; U1301.184 23.95,42.17 ; U1301.184 24.6,42.67 ; 93.22,15.32 93.22,16.26 ; 93.22,15.32 93.22,14.39 ; 93.22,15.32 94.16,15.32 ; J0401.23 18.13,9.93 ; J0401.23 16.95,12 ; J0401.23 16.95,7.85 ; J0401.23 15.77,9.93 ; U1301.440 46.15,48.83 ; U1301.440 46.9,48.08 ; U1301.440 46.15,47.32 ; U1301.440 45.4,48.08 ; 57.65,67.58 U1301.14 ; U1301.14 58.65,67.58 ; U1301.14 58.15,66.92 ; U1301.14 58.15,68.23 ; U1301.427 56.15,51.33 ; U1301.427 56.15,49.82 ; U1301.427 56.9,50.58 ; U1301.427 55.4,50.58 ; U1301.323 65.2,45.88 ; U1301.323 64.55,45.37 ; U1301.323 63.9,45.88 ; U1301.323 64.55,46.38 ; U1301.202 30.65,32.88 ; U1301.202 30.15,33.53 ; U1301.202 29.65,32.88 ; U1301.202 30.15,32.22 ; U1301.44 49.05,67.58 ; U1301.44 48.55,66.92 ; U1301.44 48.05,67.58 ; U1301.44 48.55,68.23 ; U1301.447 51.15,46.33 ; U1301.447 51.15,44.82 ; U1301.447 50.4,45.58 ; U1301.447 51.9,45.58 ; U1301.311 67.75,41.08 67.47,40.8 ; 23.95,38.97 U1301.190 ; U1301.190 23.95,39.98 ; U1301.190 24.6,39.48 ; 107.12,91.95 S1202.3 ; S1202.3 108.5,90.57 ; S1202.3 109.88,91.95 ; S1202.3 108.5,93.33 ; U1301.13 59.45,69.47 ; U1301.13 58.95,68.82 ; U1301.13 58.95,70.13 ; U1301.13 58.45,69.47 ; 68.35,61.37 U1301.375 ; U1301.375 68.35,62.38 ; U1301.375 67.7,61.88 ; U1301.375 69,61.88 ; 42.9,45.58 U1301.450 ; U1301.450 43.65,44.82 ; U1301.450 43.65,46.33 ; U1301.450 44.4,45.58 ; U1301.194 24.6,36.27 ; U1301.194 23.95,36.78 ; U1301.194 23.95,35.77 ; U1301.194 23.3,36.27 ; 55.4,48.08 U1301.436 ; U1301.436 56.15,47.32 ; U1301.436 56.15,48.83 ; U1301.436 56.9,48.08 ; U1301.154 29.65,51.98 ; U1301.154 29,51.48 ; U1301.154 30.3,51.48 ; U1301.154 29.65,50.97 ; J1002.1 25.46,3.33 ; J1002.1 24.29,4.5 ; J1002.1 23.11,3.33 ; 56.85,73.28 U1301.21 ; U1301.21 57.35,72.62 ; U1301.21 57.35,73.93 ; 40.4,48.08 U1301.442 ; U1301.442 41.15,48.83 ; U1301.442 41.9,48.08 ; U1301.442 41.15,47.32 ; 46.15,44.82 U1301.449 ; U1301.449 46.9,45.58 ; U1301.449 46.15,46.33 ; U1301.449 45.4,45.58 ; U1301.241 43.45,32.88 ; U1301.241 42.95,32.22 ; U1301.241 42.45,32.88 ; U1301.167 25.85,48.78 ; U1301.167 25.2,48.27 ; U1301.167 25.85,47.77 ; U1301.167 26.5,48.27 ; 40.85,65.67 U1301.65 ; U1301.65 41.85,65.67 ; U1301.65 41.35,66.33 ; 53.65,49.82 U1301.428 ; U1301.428 52.9,50.58 ; U1301.428 53.65,51.33 ; U1301.428 54.4,50.58 ; U1301.199 29.05,32.88 ; U1301.199 28.05,32.88 ; U1301.199 28.55,33.53 ; U1301.199 28.55,32.22 ; 4.35,89.15 J0101.3 ; J0101.3 5.83,87.22 ; J0101.3 5.83,91.08 ; J0101.3 7.3,89.15 ; 43.65,47.32 U1301.441 ; U1301.441 44.4,48.08 ; U1301.441 43.65,48.83 ; U1301.441 42.9,48.08 ; U1301.114 28.4,65.08 ; U1301.114 27.75,65.58 ; U1301.114 27.1,65.08 ; U1301.114 27.75,64.57 ; U1301.224 39.45,38.58 ; U1301.224 38.45,38.58 ; U1301.224 38.95,37.92 ; U1301.224 38.95,39.23 ; U1301.237 42.65,34.77 ; U1301.237 41.65,34.77 ; U1301.237 42.15,35.43 ; U1301.237 42.15,34.12 ; U1301.446 53.65,46.33 ; U1301.446 52.9,45.58 ; U1301.446 53.65,44.82 ; U1301.446 54.4,45.58 ; 25.2,40.27 U1301.188 ; U1301.188 26.5,40.27 ; U1301.188 25.85,39.77 ; U1301.188 25.85,40.78 ; 32.55,34.12 U1301.207 ; U1301.207 32.55,35.43 ; U1301.207 32.05,34.77 ; U1301.207 33.05,34.77 ; S1202.4 101.5,93.33 ; S1202.4 100.12,91.95 ; S1202.4 102.88,91.95 ; S1202.4 101.5,90.57 ; 1.27,3.92 J0401.21 ; J0401.21 2.45,5.6 ; J0401.21 2.45,2.25 ; J0401.21 3.63,3.92 ; U1301.413 46.9,55.58 ; U1301.413 46.15,56.33 ; U1301.413 45.4,55.58 ; U1301.413 46.15,54.82 ; 27.75,59.77 U1301.128 ; U1301.128 27.1,60.27 ; U1301.128 27.75,60.78 ; U1301.128 28.4,60.27 ; 48.65,47.32 U1301.439 ; U1301.439 48.65,48.83 ; U1301.439 47.9,48.08 ; U1301.439 49.4,48.08 ; 57.35,36.02 U1301.283 ; U1301.283 57.85,36.67 ; U1301.283 57.35,37.33 ; 113.75,68.92 J1201.1 ; J1201.1 114.62,68.05 ; J1201.1 115.5,68.92 ; J1201.1 114.62,69.8 ; U1301.396 43.65,61.33 ; U1301.396 43.65,59.82 ; U1301.396 42.9,60.58 ; U1301.396 44.4,60.58 ; J0301.16 50.03,16.54 ; J0301.16 50.86,15.71 ; J0301.16 50.03,14.89 ; J0301.16 49.21,15.71 ; U1301.189 28.4,39.48 ; U1301.189 27.75,38.97 ; U1301.189 27.75,39.98 ; U1301.189 27.1,39.48 ; U1301.392 54.4,60.58 ; U1301.392 53.65,61.33 ; U1301.392 52.9,60.58 ; U1301.392 53.65,59.82 ; U1301.274 54.95,39.23 ; U1301.274 54.95,37.92 ; U1301.274 54.45,38.58 ; U1301.274 55.45,38.58 ; U1301.426 36.9,53.08 ; U1301.426 35.4,53.08 ; U1301.426 36.15,53.83 ; U1301.426 36.15,52.32 ; U1301.415 41.15,56.33 ; U1301.415 40.4,55.58 ; U1301.415 41.15,54.82 ; U1301.415 41.9,55.58 ; 43.65,57.32 U1301.405 ; U1301.405 44.4,58.08 ; U1301.405 42.9,58.08 ; U1301.405 43.65,58.83 ; 56.6,7.09 J0301.21 ; J0301.21 54.68,9.02 ; J0301.21 56.6,10.94 ; J0301.21 58.53,9.02 ; U1301.193 25.85,37.58 ; U1301.193 25.85,36.57 ; U1301.193 26.5,37.08 ; U1301.193 25.2,37.08 ; U1205.1 19.15,69.25 ; U1205.1 22.33,66.08 ; U1205.1 15.97,66.08 ; U1205.1 19.15,62.9 ; 39.48,0.87 J0302.10 ; J0302.10 40.21,1.95 ; J0302.10 38.76,1.95 ; 95.25,9.99 J0601.3 ; J0601.3 96.12,12.02 ; J0601.3 97,9.99 ; J0601.3 96.12,7.97 ; J1201.15 115.5,82.92 ; J1201.15 114.62,83.8 ; J1201.15 113.75,82.92 ; 93.22,12.71 94.16,12.71 ; 93.22,12.71 93.22,11.77 ; 93.22,12.71 93.22,13.64 ; 32.85,32.88 U1301.211 ; U1301.211 33.35,33.53 ; U1301.211 33.85,32.88 ; U1301.211 33.35,32.22 ; 18.61,11.43 J1002.5 19.79,10.25 ; 47.75,68.82 U1301.48 ; U1301.48 48.25,69.47 ; U1301.48 47.25,69.47 ; U1301.48 47.75,70.13 ; U1301.443 38.65,48.83 ; U1301.443 37.9,48.08 ; U1301.443 39.4,48.08 ; U1301.443 38.65,47.32 ; J0601.4 97,15.68 ; J0601.4 96.12,17.7 ; J0601.4 95.25,15.68 ; J0601.4 96.12,13.65 ; 56.85,40.48 U1301.280 ; U1301.280 57.35,41.13 ; U1301.280 57.85,40.48 ; U1301.417 36.9,55.58 ; U1301.417 36.15,54.82 ; U1301.417 36.15,56.33 ; U1301.417 35.4,55.58 ; 69,50.67 U1301.341 67.7,50.67 ; 30.45,34.77 U1301.203 ; U1301.203 30.95,35.43 ; U1301.203 30.95,34.12 ; U1301.203 31.45,34.77 ; 53.53,10.19 J0301.4 ; J0301.4 52.71,11.02 ; J0301.4 54.36,11.02 ; U1301.212 34.65,34.77 ; U1301.212 33.65,34.77 ; U1301.212 34.15,35.43 ; U1301.212 34.15,34.12 ; 76.33,40.08 U1201.1 69.97,40.08 ; 40.4,60.58 U1301.397 ; U1301.397 41.15,61.33 ; U1301.397 41.15,59.82 ; U1301.397 41.9,60.58 ; J0301.20 45.39,9.02 ; J0301.20 41.54,9.02 ; J0301.20 43.47,10.94 ; J0301.20 43.47,7.09 ; U1301.372 66.45,61.58 ; U1301.372 67.1,61.08 ; U1301.372 66.45,60.57 ; U1301.372 65.8,61.08 ; 47.9,55.58 U1301.412 ; U1301.412 48.65,54.82 ; U1301.412 48.65,56.33 ; U1301.412 49.4,55.58 ; 23.95,54.97 U1301.146 24.6,55.48 ; 40.4,53.08 U1301.424 ; U1301.424 41.9,53.08 ; U1301.424 41.15,52.32 ; U1301.424 41.15,53.83 ; U1301.452 39.4,45.58 ; U1301.452 37.9,45.58 ; U1301.452 38.65,44.82 ; U1301.452 38.65,46.33 ; S1202.1 107.25,95.43 ; S1202.1 106.27,94.45 ; S1202.1 108.23,94.45 ; S1202.1 107.25,93.47 ; U1301.187 23.95,41.58 ; U1301.187 24.6,41.08 ; U1301.187 23.95,40.57 ; U1301.394 49.4,60.58 ; U1301.394 47.9,60.58 ; U1301.394 48.65,59.82 ; U1301.394 48.65,61.33 ; 11.12,87.22 J0101.2 ; J0101.2 9.65,89.15 ; J0101.2 11.12,91.08 ; J0101.2 12.6,89.15 ; 36.15,57.32 U1301.408 ; U1301.408 35.4,58.08 ; U1301.408 36.15,58.83 ; U1301.408 36.9,58.08 ; U1301.425 39.4,53.08 ; U1301.425 38.65,52.32 ; U1301.425 37.9,53.08 ; 42.9,50.58 U1301.432 ; U1301.432 44.4,50.58 ; U1301.432 43.65,49.82 ; U1301.432 43.65,51.33 ; U1301.401 53.65,58.83 ; U1301.401 54.4,58.08 ; U1301.401 52.9,58.08 ; U1301.401 53.65,57.32 ; 29.65,69.47 U1301.99 ; U1301.99 30.15,70.13 ; U1301.99 30.65,69.47 ; U1301.99 30.15,68.82 ; U1301.400 56.15,58.83 ; U1301.400 55.4,58.08 ; U1301.400 56.15,57.32 ; U1301.400 56.9,58.08 ; U1301.195 24.6,34.67 ; U1301.195 23.3,34.67 ; U1301.195 23.95,34.17 ; U1301.195 23.95,35.18 ; 32.36,1.95 J0302.11 ; J0302.11 33.09,0.87 ; J0302.11 33.81,1.95 ; 56.85,69.47 U1301.18 ; U1301.18 57.85,69.47 ; U1301.18 57.35,70.13 ; U1301.18 57.35,68.82 ; 33.35,72.62 U1301.94 ; U1301.94 33.85,73.28 ; U1301.94 33.35,73.93 ; U1301.166 24.6,49.08 ; U1301.166 23.95,48.57 ; U1301.166 23.3,49.08 ; U1301.166 23.95,49.58 ; 47.9,45.58 U1301.448 ; U1301.448 48.65,44.82 ; U1301.448 48.65,46.33 ; U1301.448 49.4,45.58 ; 67.4,35.05 67.78,34.67 U1301.301 69.33,34.67 ; U1301.403 49.4,58.08 ; U1301.403 48.65,58.83 ; U1301.403 48.65,57.32 ; U1301.403 47.9,58.08 ; U1301.451 41.9,45.58 ; U1301.451 40.4,45.58 ; U1301.451 41.15,46.33 ; U1301.451 41.15,44.82 ; 67.7,55.48 U1301.356 69,55.48 ; 23.3,71.47 U1301.106 ; U1301.106 23.95,71.98 ; U1301.106 23.95,70.97 ; U1301.106 24.6,71.47 ; 50.95,32.22 U1301.266 ; U1301.266 50.45,32.88 ; U1301.266 51.45,32.88 ; 57.35,33.53 U1301.285 57.85,32.88 ; 63.9,55.48 U1301.353 ; U1301.353 65.2,55.48 ; U1301.353 64.55,54.97
  TOP w0.5: v1(4.95,66.25) v1(4.95,62.4) v1(4.95,58.2) ; C1401.1 v1(30.15,30.75)
  INNER LAYER 2 w0.1: 18.75,59.17 v1(18.62,59.3) ; 64.25,32.67 64.15,32.77 64.15,33.45 64.1,33.5 ; v1(52.58,67.88) 52.67,67.97 v1(54.1,67.97) ; 118.3,28.15 117.8,27.65 v1(117.8,27.1)
  INNER LAYER 2 w0.3: J1101.6 114.43,62.75 ; J1101.6 115.52,61.66 ; J1101.6 113.34,61.66 ; J1101.6 114.43,60.58 ; 2.45,2.25 J0401.21 ; J0401.21 1.27,3.92 ; J0401.21 3.63,3.92 ; J0401.21 2.45,5.6 ; 93.22,11.77 93.22,12.71 ; 93.22,12.71 94.16,12.71 ; 93.22,12.71 93.22,13.64 ; 93.22,12.71 92.29,12.71 ; J1101.5 116.97,62.75 ; J1101.5 118.06,61.66 ; J1101.5 116.97,60.58 ; J1101.5 115.88,61.66 ; 9.65,89.15 J0101.2 ; J0101.2 11.12,91.08 ; J0101.2 11.12,87.22 ; J0101.2 12.6,89.15 ; 52.71,14.21 J0301.13 ; J0301.13 53.53,13.39 ; J0301.13 54.36,14.21 ; U1203.1 73.15,69.25 ; U1203.1 73.15,62.9 ; U1203.1 69.97,66.08 ; U1203.1 76.33,66.08 ; J1201.15 114.62,83.8 ; J1201.15 115.5,82.92 ; J1201.15 114.62,82.05 ; J1201.15 113.75,82.92 ; 12.07,94.32 J0101.5 ; J0101.5 10.7,96.45 ; J0101.5 13.45,96.45 ; J0101.5 12.07,98.58 ; J0301.16 50.03,16.54 ; J0301.16 50.03,14.89 ; J0301.16 50.86,15.71 ; J0301.16 49.21,15.71 ; J1201.1 114.62,69.8 ; J1201.1 115.5,68.92 ; J1201.1 113.75,68.92 ; J1201.1 114.62,68.05 ; 4.35,89.15 J0101.3 ; J0101.3 5.83,91.08 ; J0101.3 5.83,87.22 ; J0101.3 7.3,89.15 ; 106.27,94.45 S1202.1 ; S1202.1 108.23,94.45 ; S1202.1 107.25,93.47 ; S1202.1 107.25,95.43 ; J0401.22 16.95,5.6 ; J0401.22 18.13,3.92 ; J0401.22 15.77,3.92 ; J0401.22 16.95,2.25 ; J0301.7 50.86,12.52 ; J0301.7 50.03,11.69 ; J0301.7 49.21,12.52 ; J0301.7 50.03,13.34 ; 96.12,13.65 J0601.4 ; J0601.4 96.12,17.7 ; J0601.4 95.25,15.68 ; J0601.4 97,15.68 ; 41.54,14.7 J0301.19 ; J0301.19 43.47,12.77 ; J0301.19 43.47,16.62 ; J0301.19 45.39,14.7 ; S1202.3 109.88,91.95 ; S1202.3 108.5,93.33 ; S1202.3 107.12,91.95 ; S1202.3 108.5,90.57 ; 19.15,36.9 U1202.1 ; U1202.1 22.33,40.08 ; U1202.1 19.15,43.25 ; U1202.1 15.97,40.08 ; 73.15,36.9 U1201.1 ; U1201.1 73.15,43.25 ; U1201.1 76.33,40.08 ; U1201.1 69.97,40.08 ; J0101.4 2.17,98.58 ; J0101.4 0.8,96.45 ; J0101.4 3.55,96.45 ; J0101.4 2.17,94.32 ; 33.09,0.87 J0302.11 ; J0302.11 32.36,1.95 ; J0302.11 33.09,3.03 ; J0302.11 33.81,1.95 ; J0601.1 83.33,17.7 ; J0601.1 84.2,15.68 ; J0601.1 83.33,13.65 ; J0601.1 82.45,15.68 ; 15.77,9.93 J0401.23 ; J0401.23 16.95,7.85 ; J0401.23 16.95,12 ; J0401.23 18.13,9.93 ; J0302.10 39.48,3.03 ; J0302.10 40.21,1.95 ; J0302.10 39.48,0.87 ; J0302.10 38.76,1.95 ; J0401.20 2.45,12 ; J0401.20 2.45,7.85 ; J0401.20 1.27,9.93 ; J0401.20 3.63,9.93 ; S1202.4 101.5,93.33 ; S1202.4 101.5,90.57 ; S1202.4 100.12,91.95 ; S1202.4 102.88,91.95 ; J0601.3 97,9.99 ; J0601.3 96.12,7.97 ; J0601.3 95.25,9.99 ; J0601.3 96.12,12.02 ; U1205.1 22.33,66.08 ; U1205.1 19.15,62.9 ; U1205.1 15.97,66.08 ; U1205.1 19.15,69.25 ; 54.68,14.7 J0301.22 ; J0301.22 58.53,14.7 ; J0301.22 56.6,12.77 ; J0301.22 56.6,16.62 ; 41.54,9.02 J0301.20 ; J0301.20 45.39,9.02 ; J0301.20 43.47,7.09 ; J0301.20 43.47,10.94 ; J0301.21 56.6,10.94 ; J0301.21 58.53,9.02 ; J0301.21 54.68,9.02 ; J0301.21 56.6,7.09 ; 23.11,3.33 J1002.1 ; J1002.1 25.46,3.33 ; J1002.1 24.29,4.5 ; J0601.2 83.33,12.02 ; J0601.2 82.45,9.99 ; J0601.2 83.33,7.97 ; J0601.2 84.2,9.99 ; 93.22,15.32 93.22,16.26 ; 93.22,15.32 94.16,15.32 ; 93.22,15.32 93.22,14.39 ; 93.22,15.32 92.29,15.32 ; 18.61,11.43 J1002.5 ; J1002.5 19.79,10.25 ; J1002.5 20.96,11.43 ; J1002.5 19.79,12.6 ; 52.71,11.02 J0301.4 ; J0301.4 54.36,11.02 ; J0301.4 53.53,10.19
  INNER LAYER 3 w0.1: v1(31.75,71.53) 31.85,71.53 33.35,73.03 35.65,73.03 38.39,75.76 38.39,86.84 35.9,89.33 v1(35.9,89.83) ; 6.67,39.74 6.67,39.8 6.5,39.98 ; 6.67,39.74 2.48,43.94 2.48,66.72 ; 6.67,39.74 6.67,32.15 ; v1(84.15,8.03) 84.55,8.43 84.55,19.52 89.7,24.68 v1(90.47,24.68) ; v1(71.17,75.62) 71.4,75.85 86.53,75.85 88.64,73.74 ; 21.6,13.62 21.95,13.28 25.98,13.28 28.5,10.75 28.5,10.03 32.95,5.58 40.67,5.58 42.88,3.38 57,3.38 59.27,5.65 78.89,5.65 80.95,7.71 80.95,17.5 90.25,26.8 90.6,26.8 90.7,26.9 90.7,27.9 v1(90.55,28.05) ; v1(86.95,45.23) 86.85,45.12 86.85,43.88 91.75,38.98 v1(92.05,38.98) ; 91.13,96.33 90.17,96.33 89.75,95.9 89.75,95.12 91.39,93.49 ; 68.95,59.58 69.58,58.95 74.62,58.95 77.35,56.23 77.35,46.7 90.03,34.02 v1(90.03,33.48) ; 8.22,30.52 6.67,32.06 6.67,32.15 ; 91.39,93.49 91.69,93.49 91.78,93.4 v1(91.8,93.4) ; 91.39,93.49 98.58,86.3 98.58,82.75 ; v1(19.38,89.38) 19.38,89.28 19.15,89.05 17.38,89.05 17.2,89.22 v1(17.2,89.45) ; 109.2,69.8 107.05,69.8 105.47,71.38 ; 43.17,72.75 43.17,84.9 42.65,85.42 40.05,85.42 ; 1.8,18.8 1.52,19.07 1.52,19.62 1.68,19.77 1.68,19.9 ; v1(30.88,91.4) 31.8,92.33 38.1,92.33 43.8,86.62 43.8,75.15 47.67,71.28 ; v1(57.38,35.38) 57.42,35.42 59,35.42 60.3,36.73 60.3,37.87 61.45,39.02 62.92,39.02 68.83,44.92 71.38,44.92 71.95,45.5 71.95,45.77 72.55,46.38 72.95,46.38 73.08,46.5 v1(73.53,46.5) ; 21.27,34.2 21.27,32.03 19.77,30.52 8.41,30.52 ; 80.6,28.1 80.33,27.82 80.33,21.07 79.65,20.4 79,20.4 76.53,22.88 v1(74.83,22.88) ; v1(95.58,37.1) 95.45,37.1 95,37.55 ; 42.7,64.72 v1(40.88,66.55) ; 6.67,32.15 6.8,32.02 ; v1(90.58,23.88) 89.53,23.88 84.95,19.3 84.95,8.75 v1(85.85,7.85) ; 39.9,8.92 39.9,8.78 42.33,6.35 57.4,6.35 58.3,7.25 64.97,7.25 65.53,7.8 77.3,7.8 v1(77.75,7.35) 77.9,7.5 ; 92.15,80.6 92.08,80.53 80.97,80.53 80.42,81.08 73.62,81.08 69.95,84.75 69.35,84.75 69.1,85 69.1,85.3 ; 86.66,53.76 81.5,58.92 81.5,61.98 v1(81.67,62.15) ; v1(29.25,13.75) 29.07,13.93 28.57,13.93 23.8,18.7 23.8,31.88 24.77,32.85 24.77,42.05 21.7,45.12 21.7,47.95 22.93,49.17 26.52,49.17 29.05,51.7 29.05,69.03 30.52,70.5 30.52,73.9 30.62,74 30.77,74 v1(30.87,73.9) 31.24,74.28 35.6,74.28 37.49,76.16 37.49,86.24 34.4,89.33 v1(34.3,89.33) ; 89.9,29.77 89.83,29.85 88.88,29.85 88.75,29.73 ; 41.1,36.08 43.62,36.08 51.4,43.85 58.18,43.85 59.85,45.53 59.85,48.53 62.55,51.23 68.22,51.23 68.92,51.92 68.92,53.45 69.55,54.08 71.7,54.08 71.92,53.85 72.5,53.85 ; 38.12,94.12 46.15,86.1 46.15,75.75 49.25,72.65 50.33,72.65 ; 58.7,67.4 56.52,65.22 v1(56.52,65.1) ; 64.97,67.77 69,71.8 69.85,71.8 70.23,71.42 72.43,71.42 73.3,72.3 ; 88.3,32.05 88.3,33.9 76.4,45.8 76.4,55.7 75.78,56.33 72.05,56.33 71.65,55.92 69.47,55.92 67.95,54.4 67.95,52.23 67.75,52.02 63.62,52.02 v1(63.38,52.27) ; v1(36.23,93.12) 36.2,93.12 36.1,93.03 34.35,93.03 v1(34.08,93.3) 34.08,94.1 33.85,94.33 29.35,94.33 27.15,92.12 v1(27.15,91.4) ; v1(49.88,63.38) 57.17,63.38 60.36,66.56 64.45,66.56 68.92,71.03 73.05,71.03 ; 65.01,67.83 64.15,66.96 60.14,66.96 58.75,65.58 v1(58.3,65.58) 58.3,66.38 59,67.08 ; 86.08,26.32 87.62,27.88 ; 58.5,67.83 56.67,66 56.17,66 56.05,65.88 v1(56.05,64.65) ; 101.53,38.1 101.33,37.9 99.12,37.9 98.67,38.35 v1(98.67,38.5) 98.75,38.58 98.75,38.83 99.1,39.17 101.22,39.17 101.47,38.92 v1(101.47,38.55) ; 113.08,80.15 110.85,77.92 110.85,70.25 109.58,68.97 106.67,68.97 105.15,70.5 101.97,70.5 97.7,66.22 94.62,66.22 94.1,66.75 93.35,66.75 93.2,66.6 v1(93.2,66.03) 93.25,66.03 93.45,65.83 97.89,65.83 102.17,70.1 104.95,70.1 106.47,68.58 109.78,68.58 111.25,70.05 111.25,77.72 113.28,79.75 ; 89.15,28.9 89.15,26.88 80.15,17.88 80.15,8.15 78.45,6.45 58.77,6.45 56.55,4.22 54.27,4.22 ; v1(21.77,91.38) 21.77,91.25 21.48,90.95 19.93,90.95 19.82,91.05 v1(19.82,91.4) 19.82,91.45 24.2,95.83 26.18,95.83 ; 65.15,83.08 69.03,79.2 91.63,79.2 ; 87.92,33.98 76.2,45.7 v1(76.2,45.95) ; 95.02,33.67 95.02,34.48 93.05,36.45 91.22,36.45 79.83,47.85 79.83,57.38 79.62,57.58 79.62,57.6 78.42,58.8 78.42,62.1 v1(78.3,62.23) 78.42,62.35 78.42,62.65 78.95,63.17 78.95,69.28 78.85,69.38 v1(78.65,69.38) ; v1(31.73,4.92) 31.8,4.92 32.25,4.47 40.12,4.47 42.38,2.23 57.48,2.23 59.75,4.5 79.62,4.5 80,4.88 v1(80,6.03) ; 38,91.53 33.05,91.53 v1(32.92,91.4) ; v1(53.35,40.33) 53.62,40.6 55.5,40.6 56.1,40 56.67,40 61.71,45.04 61.71,46.7 64.61,49.6 69.05,49.6 70.88,51.42 73.2,51.42 73.65,51.88 73.65,52.4 72.85,53.2 70.85,53.2 v1(70.62,53.42) 70.12,52.92 70.12,52.52 68.42,50.83 62.88,50.83 60.29,48.24 60.29,45.38 58.36,43.45 51.6,43.45 44.25,36.1 ; v1(69.22,85.78) 69.55,85.78 73.85,81.47 78.47,81.47 80.22,83.22 ; v1(79.35,71.67) 79.28,71.75 79.1,71.58 78.22,71.58 77.38,72.42 77.22,72.58 74.7,72.58 74.03,71.9 ; 71.86,47.74 v1(71.58,47.45) 71.62,47.4 71.62,47.2 71.12,46.7 68.4,46.7 62.26,40.56 60.31,40.56 59.35,39.6 59.35,38.75 ; 41.08,6.35 41,6.42 33.27,6.42 29.38,10.32 29.38,11.07 26.32,14.12 22.43,14.12 20.3,16.25 20.3,16.62 ; 68.97,57.6 75.2,57.6 76.8,56 76.8,46.05 88.8,34.05 88.8,33.4 88.91,33.29 v1(88.99,33.29) ; 39.45,67.72 39.45,66.18 40.15,65.48 40.95,65.48 40.6,65.12 v1(40.55,65.12) ; 56.02,37.01 56.02,36.48 56.27,36.23 59.2,36.23 59.9,36.92 59.9,38.05 61.3,39.45 62.73,39.45 68.6,45.33 71.17,45.33 71.55,45.7 71.55,46 71.78,46.23 v1(71.78,46.48) 71.78,46.5 71.53,46.25 68.62,46.25 62.42,40.05 61.08,40.05 59.35,38.32 59.35,37.23 58.92,36.8 57.05,36.8 v1(56.5,37.35) ; v1(76.22,19.07) 76.33,18.98 79.78,18.98 81.5,20.7 81.5,26.02 81.6,26.12 82.97,26.12 84.08,25.02 84.47,25.02 84.88,25.43 v1(84.88,26.18) ; 66.08,31.05 66.42,31.05 67.95,32.58 68.22,32.58 ; 51.95,42.65 58.69,42.65 61.25,45.2 61.25,46.87 64.4,50.02 68.85,50.02 70.7,51.88 72.4,51.88 v1(72.58,52.05) ; 89.75,98.5 89.75,96.92 89.35,96.53 89.35,94.92 97.88,86.4 97.88,84.15 97.78,84.05 96.38,84.05 v1(96.35,84.03) ; v1(54.1,67.97) v1(55.73,67.97) ; 93.92,32.58 94.45,33.1 94.45,34.33 92.78,36 91.05,36 79.39,47.66 79.39,57.16 77.26,59.29 77.26,62.71 78.28,63.73 78.28,68.58 77.42,69.42 v1(77.42,69.83) ; 81.9,57.7 81.9,48.23 84.28,45.85 84.28,45.2 91.53,37.95 96.17,37.95 ; 93.3,82.1 92.7,82.1 ; 68.42,66.58 68.42,64.28 72.17,60.52 74.5,60.52 78.35,56.67 78.35,47.2 90.62,34.92 91.92,34.92 92.3,34.55 92.3,32.1 v1(92.15,31.95) ; v1(93.47,34.15) 93.47,34.42 92.35,35.55 90.9,35.55 78.95,47.5 78.95,57 76.62,59.33 v1(76.62,61.3) 76.62,63.3 77.5,64.17 77.5,68.35 76.45,69.4 76.1,69.4 v1(76.03,69.47) ; 97.4,85.35 v1(97.42,85.38) ; v1(55.02,39.77) 55.88,38.92 56.75,38.92 57.1,39.27 57.1,39.83 62.19,44.91 62.19,46.46 64.92,49.2 69.38,49.2 70.03,49.85 70.6,49.85 70.97,50.23 v1(70.97,50.58)
  INNER LAYER 3 w0.15: 22.48,31.95 22.48,32.45 23.34,33.31 23.34,41.64 20.3,44.67 20.3,48.45 22.35,50.5 25.94,50.5 27.7,52.26 27.7,71.67 28,71.97 28,72.95 27.82,73.12 26.57,73.12 26.43,73.28 v1(26.25,73.28) ; 22.48,31.95 22.48,31.73 v1(22.27,31.52) ; 22.48,31.95 21.65,31.12 22.2,30.57 ; v1(3.4,69.55) 3.2,69.35 2.17,69.35 1.6,68.78 1.6,43.45 5.85,39.2 5.85,31.5 7.72,29.62 20.32,29.62 20.32,29.82 21.45,30.95 ; v1(22.23,30.12) 22.38,29.98 22.38,17.45 v1(21.8,16.88)
  INNER LAYER 3 w0.2: 30.09,12.55 28.88,12.55 26.65,14.78 22.77,14.78 21.8,15.75 v1(21.8,16.88) ; 3.98,15.18 4.72,15.18 v1(4.88,15.03)
  INNER LAYER 3 w0.3: 52.71,11.02 J0301.4 ; J0301.4 53.53,10.19 ; J0301.4 54.36,11.02 ; 73.15,36.9 U1201.1 ; U1201.1 73.15,43.25 ; U1201.1 69.97,40.08 ; J1002.1 24.29,4.5 ; J1002.1 25.46,3.33 ; J1002.1 23.11,3.33 ; 32.36,1.95 J0302.11 ; J0302.11 33.09,3.03 ; J0302.11 33.09,0.87 ; J0302.11 33.81,1.95 ; 114.62,68.05 J1201.1 ; J1201.1 115.5,68.92 ; J1201.1 114.62,69.8 ; J1201.1 113.75,68.92 ; J0301.22 56.6,16.62 ; J0301.22 58.53,14.7 ; J0301.22 54.68,14.7 ; J0301.22 56.6,12.77 ; 2.45,2.25 J0401.21 ; J0401.21 1.27,3.92 ; J0401.21 3.63,3.92 ; J0401.21 2.45,5.6 ; 101.5,90.57 S1202.4 ; S1202.4 102.88,91.95 ; S1202.4 101.5,93.33 ; S1202.4 100.12,91.95 ; 41.54,9.02 J0301.20 ; J0301.20 43.47,10.94 ; J0301.20 43.47,7.09 ; J0301.20 45.39,9.02 ; S1202.3 108.5,93.33 ; S1202.3 108.5,90.57 ; S1202.3 107.12,91.95 ; S1202.3 109.88,91.95 ; J0401.20 3.63,9.93 ; J0401.20 1.27,9.93 ; J0401.20 2.45,12 ; J0401.20 2.45,7.85 ; J0601.1 83.33,17.7 ; J0601.1 83.33,13.65 ; J0601.1 82.45,15.68 ; J0601.1 84.2,15.68 ; J0401.23 16.95,12 ; J0401.23 18.13,9.93 ; J0401.23 16.95,7.85 ; J0401.23 15.77,9.93 ; U1203.1 73.15,69.25 ; U1203.1 73.15,62.9 ; U1203.1 69.97,66.08 ; U1203.1 76.33,66.08 ; J0302.10 40.21,1.95 ; J0302.10 39.48,0.87 ; J0302.10 39.48,3.03 ; J0302.10 38.76,1.95 ; 12.07,94.32 J0101.5 ; J0101.5 13.45,96.45 ; J0101.5 10.7,96.45 ; J0101.5 12.07,98.58 ; v1(45,99.2) 45.15,99.35 84.25,99.35 v1(84.35,99.25) ; J0301.21 58.53,9.02 ; J0301.21 56.6,7.09 ; J0301.21 54.68,9.02 ; J0301.21 56.6,10.94 ; J0101.4 2.17,98.58 ; J0101.4 0.8,96.45 ; J0101.4 3.55,96.45 ; J0101.4 2.17,94.32 ; U1205.1 22.33,66.08 ; U1205.1 15.97,66.08 ; U1205.1 19.15,69.25 ; U1205.1 19.15,62.9 ; J0601.4 97,15.68 ; J0601.4 95.25,15.68 ; J0601.4 96.12,13.65 ; J0601.4 96.12,17.7 ; 83.33,7.97 J0601.2 ; J0601.2 84.2,9.99 ; J0601.2 83.33,12.02 ; J0601.2 82.45,9.99 ; J1101.5 118.06,61.66 ; J1101.5 116.97,60.58 ; J1101.5 115.88,61.66 ; J1101.5 116.97,62.75 ; 107.25,93.47 S1202.1 ; S1202.1 106.27,94.45 ; S1202.1 108.23,94.45 ; S1202.1 107.25,95.43 ; 93.22,12.71 94.16,12.71 ; 93.22,12.71 92.29,12.71 ; 93.22,12.71 93.22,11.77 ; 93.22,12.71 93.22,13.64 ; J0101.3 7.3,89.15 ; J0101.3 4.35,89.15 ; J0101.3 5.83,91.08 ; J0101.3 5.83,87.22 ; J0401.22 16.95,5.6 ; J0401.22 18.13,3.92 ; J0401.22 16.95,2.25 ; J0401.22 15.77,3.92 ; J1002.5 20.96,11.43 ; J1002.5 19.79,10.25 ; J1002.5 19.79,12.6 ; J1002.5 18.61,11.43 ; 114.43,60.58 J1101.6 ; J1101.6 114.43,62.75 ; J1101.6 115.52,61.66 ; J1101.6 113.34,61.66 ; J0301.19 45.39,14.7 ; J0301.19 41.54,14.7 ; J0301.19 43.47,16.62 ; J0301.19 43.47,12.77 ; 15.97,40.08 U1202.1 ; U1202.1 22.33,40.08 ; U1202.1 19.15,43.25 ; U1202.1 19.15,36.9 ; 50.03,11.69 J0301.7 ; J0301.7 50.86,12.52 ; J0301.7 50.03,13.34 ; J0301.7 49.21,12.52 ; 53.53,13.39 J0301.13 ; J0301.13 52.71,14.21 ; J0301.13 54.36,14.21 ; 93.22,15.32 94.16,15.32 ; 93.22,15.32 93.22,16.26 ; 93.22,15.32 93.22,14.39 ; 93.22,15.32 92.29,15.32 ; 49.21,15.71 J0301.16 ; J0301.16 50.03,14.89 ; J0301.16 50.03,16.54 ; J0601.3 96.12,12.02 ; J0601.3 95.25,9.99 ; J0601.3 97,9.99 ; J0601.3 96.12,7.97 ; 115.5,82.92 J1201.15 113.75,82.92 ; J0101.2 12.6,89.15 ; J0101.2 11.12,91.08 ; J0101.2 11.12,87.22 ; J0101.2 9.65,89.15
  BOTTOM w0.075: 104.62,56.88 U1102.D2
  BOTTOM w0.1: 9.32,47.38 9.43,47.27 13.07,47.27 16.65,50.85 16.65,53.67 ; 18.02,53.75 17.4,53.12 17.4,49.88 13.4,45.88 11.72,45.88 ; 76.25,47.48 76.05,47.27 76.05,46.1 v1(76.2,45.95) ; 62.83,73.78 62.83,73.83 v1(62.45,74.2) ; 62.83,73.78 63.1,74.05 v1(64.6,74.05) ; 62.83,73.78 R0530.1 ; 13.25,64.08 13.25,64 13.62,63.62 ; 110.65,30.52 111.6,31.48 111.6,36.85 111.47,36.98 C0987.2 ; v1(18.62,59.3) 18.38,59.3 14.97,55.9 14.97,52.17 13.28,50.48 9.43,50.48 9.32,50.38 ; C0708.1 v1(85.88,33.23) ; 59.15,81.92 59.7,82.47 61.6,82.47 ; 107.03,23.05 106.78,22.8 106.78,20.32 107.5,19.6 ; v1(18.43,57.52) 15.85,54.95 15.85,51.55 13.18,48.88 11.72,48.88 ; 103,22.85 103,22.55 103.33,22.23 103.33,21.35 ; 107.84,11.29 107.2,11.93 107.2,18.88 106.08,20 106.08,22.77 105.88,22.98 ; 72.78,34.25 72.75,34.23 70.97,34.23 70.95,34.25 ; 65.53,28.52 v1(65.53,28.4) ; 109.92,11.1 108,13.03 108,19.1 107.5,19.6 ; 107.5,19.6 108.78,20.88 ; v1(99.17,47.02) 98.97,46.83 97.5,46.83 97.47,46.85 96.58,46.85 96.55,46.83 95.4,46.83 94.9,47.33 93.12,47.33 92.03,48.42 92.03,48.73 v1(92.4,49.1) ; 82.12,29.62 82.1,29.6 64.55,29.6 64.42,29.73 63.92,29.23 v1(63.9,29.23) ; 82.12,29.62 81.92,29.82 ; 82.12,29.62 84.25,31.75 v1(85.67,31.75) 92.35,31.75 ; 9.32,44.38 13.62,44.38 18.27,49.02 18.27,50.33 18.4,50.45 v1(18.4,50.75) ; 92.35,31.75 v1(92.15,31.95) ; 92.35,31.75 94.83,31.75 95.6,32.52 95.6,36.27 97.12,37.8 98.33,37.8 98.67,38.15 v1(98.67,38.5) 98.67,38.88 99.03,39.23 101.2,39.23 101.45,38.98 ; C0917.1 90.26,44.3 89.58,44.3 88.75,45.12 v1(88.75,46.58) 88.75,51.6 91.38,54.23 93.1,54.23 93.45,53.88 96.6,53.88 97.15,53.33 102.92,53.33 103.8,52.45 v1(103.95,52.45) ; C0711.1 85.78,32.3 v1(85.85,32.23) ; 102.58,41.38 102.58,39.83 101.47,38.73 v1(101.47,38.55) ; 101.47,32.8 101.47,32.73 101.3,32.55 101.28,32.55 ; 73.35,28.75 v1(73.35,28.62) ; 11.18,62.52 10.8,62.52 ; 105.75,11.1 105.75,16.8 100.83,21.73 100.83,22.6 ; 65.88,34.1 65.28,34.1 65.17,34 ; v1(100.8,45.8) 100.65,45.95 94.97,45.95 94.42,46.5 92.6,46.5 91.17,47.92 v1(90.72,47.92) ; 94.28,45.02 93.83,45.48 91.88,45.48 91.1,46.25 90.22,46.25 89.75,46.73 89.75,48.12 90.05,48.42 v1(90.58,48.42) ; R0901.2 114.3,47.75 v1(114.62,47.42) ; 108.78,20.88 109.28,21.38 109.28,22.45 108.62,23.1 ; 108.78,20.88 108.78,20.73 v1(108.88,20.62) ; C0707.1 85.67,34.08 v1(85.85,34.25) ; 104.88,56.88 104.62,56.88 ; 110.65,24.05 110.53,23.93 110.53,20.62 109.08,19.18 109.08,14.35 112.03,11.4 ; 105.05,11.32 105.05,16.5 99.95,21.6 99.95,22.6 100.08,22.73 ; 61.62,29.82 61.42,29.62 60.92,30.12 59.6,28.8 59.6,28.45 60.23,27.82 60.55,27.82 v1(60.8,28.07) v1(64.85,28.07) ; v1(18.07,60.38) 18.07,60.23 14.18,56.33 14.18,53.02 13.03,51.88 11.72,51.88 ; v1(30.73,88.75) 30.35,88.75 30.12,88.53 14.2,88.53 12.43,86.75 v1(12.43,86.4) ; 66.33,28.65 72.53,28.65 ; 78.88,48.38 77.15,48.38 ; 101.1,38.17 99.53,36.6 C0919.2 98.47,36.77 97.22,36.77 96.45,36 96.45,31.93 95.3,30.77 84.45,30.77 82.25,28.57 74.03,28.57 ; 62.4,82.33 61.67,82.33
  BOTTOM w0.2: X0901.4 v1(110.88,44.58) ; C0986.2 109.9,36.98 109.55,36.62 109.55,35.75 110.5,34.8 110.5,32.7 110.22,32.42 108.45,32.42
  BOTTOM w0.25: R1004.1 13.25,73.97 v1(13.53,74.25) ; C1055.1 19.3,77 17.62,78.67 17.62,81.58 17.93,81.88 17.93,83.6 18.52,84.2 23.25,84.2 23.68,83.78 v1(23.88,83.78)
  BOTTOM w0.3: J0401.23 16.95,12 ; J0401.23 18.13,9.93 ; J0401.23 15.77,9.93 ; J0401.23 16.95,7.85 ; 39.48,0.87 J0302.10 ; J0302.10 40.21,1.95 ; J0302.10 39.48,3.03 ; J0302.10 38.76,1.95 ; J1101.6 114.43,62.75 ; J1101.6 113.34,61.66 ; J1101.6 115.52,61.66 ; 16.95,2.25 J0401.22 ; J0401.22 15.77,3.92 ; J0401.22 18.13,3.92 ; J0401.22 16.95,5.6 ; J0301.20 45.39,9.02 ; J0301.20 43.47,7.09 ; J0301.20 41.54,9.02 ; J0301.20 43.47,10.94 ; 83.33,13.65 J0601.1 ; J0601.1 84.2,15.68 ; J0601.1 82.45,15.68 ; J0601.1 83.33,17.7 ; J0101.3 5.83,91.08 ; J0101.3 5.83,87.22 ; J0101.3 7.3,89.15 ; J0101.3 4.35,89.15 ; J0301.7 50.86,12.52 ; J0301.7 50.03,13.34 ; J0301.7 49.21,12.52 ; J0301.7 50.03,11.69 ; J0101.4 3.55,96.45 ; J0101.4 0.8,96.45 ; J0101.4 2.17,98.58 ; J0101.4 2.17,94.32 ; J0301.4 54.36,11.02 ; J0301.4 52.71,11.02 ; J0301.4 53.53,10.19 ; J0601.3 96.12,12.02 ; J0601.3 96.12,7.97 ; J0601.3 95.25,9.99 ; J0601.3 97,9.99 ; J0101.5 12.07,98.58 ; J0101.5 13.45,96.45 ; J0101.5 10.7,96.45 ; J0101.5 12.07,94.32 ; J0301.19 43.47,16.62 ; J0301.19 43.47,12.77 ; J0301.19 45.39,14.7 ; J0301.19 41.54,14.7 ; X0901.2 v1(112.83,42.3) ; J1201.1 115.5,68.92 ; J1201.1 113.75,68.92 ; J1201.1 114.62,68.05 ; J1201.1 114.62,69.8 ; S1202.1 108.23,94.45 ; S1202.1 107.25,95.43 ; S1202.1 107.25,93.47 ; S1202.1 106.27,94.45 ; S1202.3 109.88,91.95 ; S1202.3 107.12,91.95 ; S1202.3 108.5,93.33 ; S1202.3 108.5,90.57 ; 92.29,15.32 93.22,15.32 ; 93.22,15.32 93.22,14.39 ; 93.22,15.32 94.16,15.32 ; 93.22,15.32 93.22,16.26 ; J0301.16 50.86,15.71 ; J0301.16 49.21,15.71 ; J0301.16 50.03,16.54 ; J0301.16 50.03,14.89 ; 115.88,61.66 J1101.5 ; J1101.5 118.06,61.66 ; J1101.5 116.97,62.75 ; 9.65,89.15 J0101.2 ; J0101.2 11.12,87.22 ; J0101.2 11.12,91.08 ; J0101.2 12.6,89.15 ; J0401.20 3.63,9.93 ; J0401.20 1.27,9.93 ; J0401.20 2.45,7.85 ; J0401.20 2.45,12 ; J0301.22 58.53,14.7 ; J0301.22 54.68,14.7 ; J0301.22 56.6,12.77 ; J0301.22 56.6,16.62 ; 53.53,13.39 J0301.13 ; J0301.13 52.71,14.21 ; J0301.13 54.36,14.21 ; S1202.4 101.5,93.33 ; S1202.4 100.12,91.95 ; S1202.4 101.5,90.57 ; S1202.4 102.88,91.95 ; 114.62,82.05 J1201.15 ; J1201.15 113.75,82.92 ; J1201.15 115.5,82.92 ; J1201.15 114.62,83.8 ; 93.22,12.71 94.16,12.71 ; 93.22,12.71 93.22,13.64 ; 93.22,12.71 92.29,12.71 ; 93.22,12.71 93.22,11.77 ; J0601.2 84.2,9.99 ; J0601.2 83.33,7.97 ; J0601.2 82.45,9.99 ; J0601.2 83.33,12.02 ; J1002.1 24.29,4.5 ; J1002.1 25.46,3.33 ; J1002.1 23.11,3.33 ; J1002.5 20.96,11.43 ; J1002.5 18.61,11.43 ; J1002.5 19.79,10.25 ; J1002.5 19.79,12.6 ; J0301.21 58.53,9.02 ; J0301.21 54.68,9.02 ; J0301.21 56.6,10.94 ; J0301.21 56.6,7.09 ; 96.12,13.65 J0601.4 ; J0601.4 95.25,15.68 ; J0601.4 96.12,17.7 ; J0601.4 97,15.68 ; 30.1,33.5 C0602.1 ; 32.36,1.95 J0302.11 ; J0302.11 33.09,0.87 ; J0302.11 33.09,3.03 ; J0302.11 33.81,1.95 ; 2.45,2.25 J0401.21 ; J0401.21 1.27,3.92 ; J0401.21 2.45,5.6 ; J0401.21 3.63,3.92
  vias: v1(0.8,66.67) v1(0.78,63.95) v1(0.85,62.05) v1(0.82,59.33) v1(0.8,56.4) v1(0.78,53.67) v1(0.8,51.9) v1(0.78,50.17) v1(0.8,48.62) v1(0.75,47.45) v1(0.82,46.25) v1(0.82,44.45) v1(0.85,25.3) v1(0.8,22.4) v1(0.82,20.27) v1(0.82,18.12) v1(0.82,16.05) v1(0.78,14.5) v1(0.8,10.93) v1(0.93,70.7) v1(0.93,42.67) v1(0.95,41.3) v1(0.9,39.5) v1(0.95,37.88) v1(0.93,36.2) v1(0.95,26.8) v1(0.95,13.4) v1(0.9,12.65) v1(0.88,9.22) v1(0.88,7.33) v1(0.97,78.33) v1(1.12,31.52) v1(1.1,1.82) v1(1.25,73.4) v1(1.4,72.3) v1(1.7,6.05) v1(2.05,22.43) v1(2.08,93.2) v1(2.15,70.78) v1(2.23,20.12) v1(2.27,15.25) v1(2.35,72.55) v1(2.38,26.05) v1(2.62,41.2) v1(2.6,24.32) v1(2.58,23.55) v1(2.6,7.3) v1(2.73,56.6) v1(2.7,39.27) v1(2.75,53.98) v1(2.8,52.77) v1(2.75,21.2) v1(2.9,78.53) v1(2.85,67.38) v1(2.85,64.4) v1(2.9,62.33) v1(2.85,60.33) v1(2.92,58.35) v1(2.9,44.33) v1(2.88,37.65) v1(2.9,1.2) v1(2.95,66.45) v1(3.08,47.52) v1(3.15,46.5) v1(3.17,51.9) v1(3.27,72.05) v1(3.27,48.62) v1(3.27,43.75) v1(3.4,23.48) v1(3.48,16.43) v1(3.58,93.17) v1(3.67,24.15) v1(3.77,52.92) v1(3.77,49.38) v1(3.9,72.8) v1(3.95,98.88) v1(3.95,7.3) v1(4.12,71.5) v1(4.1,36.6) v1(4.08,5.4) v1(4.15,53.98) v1(4.15,3.08) v1(4.28,91.65) v1(4.35,26.5) v1(4.4,97.42) v1(4.42,87) v1(4.42,31.55) v1(4.45,86.38) v1(4.45,85.75) v1(4.47,44.3) v1(4.47,42.58) v1(4.53,39.12) v1(4.7,72.83) v1(4.7,69.83) v1(4.72,50.05) v1(4.75,49.38) v1(4.75,18.38) v1(4.75,13) v1(4.88,78.12) v1(4.92,67.95) v1(4.92,64.28) v1(4.97,87) v1(5,86.38) v1(5.05,85.72) v1(4.95,37.58) v1(5.25,93.17) v1(5.2,83.8) v1(5.2,82.25) v1(5.2,41.92) v1(5.17,30.75) v1(5.22,17.95) v1(5.3,51.2) v1(5.35,1.25) v1(5.38,27.45) v1(5.5,98.85) v1(5.5,7.3) v1(5.58,14.22) v1(5.72,22.23) v1(5.67,5.38) v1(5.85,92.35) v1(5.8,26.3) v1(5.8,3) v1(5.9,18.02) v1(6.05,86.7) v1(5.95,15.05) v1(6.1,52.15) v1(6.2,9.47) v1(6.28,28.27) v1(6.3,13) v1(6.38,27.2) v1(6.55,97.45) v1(6.6,46.6) v1(6.58,20.07) v1(6.72,91.58) v1(6.7,84.72) v1(6.72,45.77) v1(6.7,42.25) v1(6.65,22.55) v1(6.92,85.3) v1(6.9,47.5) v1(6.92,5.45) v1(7.05,98.8) v1(7.25,43.45) v1(7.33,4.15) v1(7.45,93.15) v1(7.47,33.4) v1(7.62,12.95) v1(7.6,2.12) v1(7.62,1.02) v1(7.72,78.45) v1(7.7,77.42) v1(7.7,76.62) v1(7.7,75.88) v1(7.7,75.12) v1(7.7,74.3) v1(7.7,73.55) v1(7.7,72.67) v1(7.7,71.9) v1(7.7,69.83) v1(7.7,69.3) v1(7.7,66.75) v1(7.7,65.33) v1(7.7,63.75) v1(7.7,59.52) v1(7.7,58.88) v1(7.7,58.25) v1(7.7,57.62) v1(7.7,55.58) v1(7.7,55.02) v1(7.7,53.05) v1(7.65,48.12) v1(7.65,47.35) v1(7.65,42.45) v1(7.67,27.9) v1(7.65,27.27) v1(7.65,9.1) v1(7.85,23.9) v1(7.8,23.3) v1(7.97,22.55) v1(8.25,97.28) v1(8.25,95.55) v1(8.3,8.3) v1(8.43,18.93) v1(8.5,93.9) v1(8.75,98.78) v1(8.8,87.8) v1(8.75,85.95) v1(8.75,21.38) v1(8.78,17.95) v1(8.93,89.75) v1(9,3.7) v1(9.1,13.85) v1(9.07,7.08) v1(9.2,9.45) v1(9.38,93.12) v1(9.47,91.28) v1(9.5,18.1) v1(9.72,87.28) v1(9.93,12.72) v1(9.95,5.72) v1(9.97,8.25) v1(10.12,19.6) v1(10.22,22.45) v1(10.25,15) v1(10.2,7.28) v1(10.3,0.9) v1(10.43,1.93) v1(10.53,85.88) v1(10.62,85.3) v1(10.7,9.47) v1(10.85,94.35) v1(10.85,13.93) v1(10.9,22.68) v1(11,25.85) v1(11.07,16.45) v1(11.1,5.72) v1(11.2,85.85) v1(11.15,85.3) v1(11.5,6.92) v1(11.7,85.3) v1(11.65,76.45) v1(11.75,75.95) v1(11.75,19.3) v1(11.85,3.7) v1(12.03,76.83) v1(12.03,5.72) v1(12.05,21.45) v1(12.15,93.47) v1(12.2,76.3) v1(12.22,24.6) v1(12.3,9.38) v1(12.4,18.62) v1(12.4,0.88) v1(12.53,7.53) v1(12.62,91.1) v1(12.57,76.78) v1(12.55,15.25) v1(12.62,12.82) v1(12.72,24.1) v1(12.82,13.68) v1(12.78,8.35) v1(12.9,74.2) v1(13.12,15.25) v1(13.22,94.4) v1(13.25,68.7) v1(13.25,68.1) v1(13.25,67.58) v1(13.25,67.05) v1(13.25,66.5) v1(13.25,65.92) v1(13.25,58.25) v1(13.25,55.52) v1(13.25,54.98) v1(13.25,54.17) v1(13.25,53.3) v1(13.25,23.57) v1(13.25,20.62) v1(13.3,98.4) v1(13.35,3.55) v1(13.38,19.8) v1(13.47,2) v1(13.65,18.9) v1(13.75,23.07) v1(13.88,14.82) v1(13.95,5.4) v1(14,9.35) v1(14.12,90.05) v1(14.07,7.58) v1(14.18,91.3) v1(14.32,98.88) v1(14.35,93.6) v1(14.6,88.03) v1(14.93,89.38) v1(14.88,16.45) v1(14.97,4.05) v1(15.12,99) v1(15.18,1.1) v1(15.43,5.35) v1(15.47,72.33) v1(15.53,18.02) v1(15.5,13.82) v1(15.57,11.12) v1(15.55,9.12) v1(15.72,89.33) v1(15.7,37.7) v1(15.8,49.9) v1(15.8,48.15) v1(15.82,45.67) v1(15.88,35.35) v1(15.9,32.5) v1(16,68.12) v1(16,58.23) v1(16.02,34.25) v1(16.02,20.5) v1(16.12,55.42) v1(16.25,46.7) v1(16.2,28.12) v1(16.18,19.73) v1(16.32,18.57) v1(16.43,58.65) v1(16.43,50.67) v1(16.4,48.77) v1(16.35,14.97) v1(16.48,36.55) v1(16.5,12.22) v1(16.6,99) v1(16.82,59.3) v1(16.77,56.12) v1(16.88,54.25) v1(16.88,45.42) v1(16.9,34.48) v1(17.15,96.95) v1(17.12,94.85) v1(17.05,93.85) v1(17.1,49.48) v1(17.05,36) v1(17.4,97.6) v1(17.5,59.73) v1(17.5,56.8) v1(17.52,54.98) v1(17.6,53.23) v1(17.6,52.12) v1(17.6,12.38) v1(17.82,95.8) v1(17.77,35.27) v1(17.75,7.62) v1(17.95,90.1) v1(17.95,34.12) v1(17.88,1.02) v1(18,58.65) v1(18.05,47.25) v1(18.1,44.48) v1(18.1,31.68) v1(18.2,45.62) v1(18.2,18.12) v1(18.23,15.1) v1(18.38,99.25) v1(18.4,94.7) v1(18.35,60.88) v1(18.35,56.98) v1(18.35,55.85) v1(18.35,55.05) v1(18.35,53.95) v1(18.35,52.75) v1(18.43,49.48) v1(18.43,25.9) v1(18.4,19.2) v1(18.48,72.4) v1(18.48,13.7) v1(18.62,93.08) v1(18.57,91.97) v1(18.6,34.6) v1(18.62,17.07) v1(18.62,5.15) v1(18.7,46.58) v1(18.75,48) v1(18.8,44.88) v1(18.88,9.57) v1(18.93,3.77) v1(18.98,97.1) v1(19.12,15.32) v1(19.25,70.95) v1(19.25,8.15) v1(19.5,99.25) v1(19.52,62.33) v1(19.52,61.45) v1(19.52,35.85) v1(19.65,26.18) v1(19.8,53.2) v1(19.8,49.52) v1(19.75,2.5) v1(19.95,93.78) v1(20,50.45) v1(20.02,33.38) v1(20.05,35.3) v1(20.2,94.38) v1(20.25,36.35) v1(20.25,18.7) v1(20.27,17.6) v1(20.4,31.85) v1(20.43,25.45) v1(20.48,99.25) v1(20.65,53.12) v1(20.65,7.85) v1(20.68,95.12) v1(20.8,92.7) v1(20.77,90.72) v1(20.75,33.02) v1(20.95,88.7) v1(20.95,73.25) v1(20.85,50.58) v1(20.93,30.1) v1(21.02,74.7) v1(21.15,72.53) v1(21.1,62.88) v1(21.12,13.38) v1(21.18,57.4) v1(21.4,12.78) v1(21.5,53.4) v1(21.55,99.2) v1(21.62,97.53) v1(21.57,95.88) v1(21.55,94.1) v1(21.57,57.77) v1(21.62,52.5) v1(21.57,36.92) v1(21.55,30.07) v1(21.73,90.75) v1(21.68,88.7) v1(21.68,56.05) v1(21.8,73.1) v1(21.85,34.62) v1(21.85,27.7) v1(22.02,72.35) v1(22,33.77) v1(22.15,94.15) v1(22.12,71.58) v1(22.12,35.45) v1(22.15,15.88) v1(22.2,62.83) v1(22.2,62.2) v1(22.18,27) v1(22.3,4.92) v1(22.4,88.7) v1(22.4,7.9) v1(22.48,51.65) v1(22.7,99.2) v1(22.68,90.75) v1(22.8,53.02) v1(22.77,52.2) v1(22.93,15.05) v1(23.1,52.6) v1(23.1,51.73) v1(23.23,9.28) v1(23.35,95.38) v1(23.52,91.4) v1(23.55,90.78) v1(23.68,95.88) v1(23.75,4.97) v1(24.32,12.05) v1(24.45,15.18) v1(24.5,92.7) v1(24.62,10.25) v1(24.6,8.03) v1(24.75,99.25) v1(25,46.8) v1(25.07,83.65) v1(25.32,90.75) v1(25.32,5.08) v1(25.4,25.12) v1(25.43,12.93) v1(25.52,91.4) v1(25.8,15.2) v1(25.88,24) v1(25.85,23.43) v1(25.93,9.07) v1(25.98,81.42) v1(26.15,27.07) v1(26.12,4.78) v1(26.25,72.47) v1(26.2,69.92) v1(26.3,90.7) v1(26.32,74.53) v1(26.32,60.27) v1(26.27,58.73) v1(26.32,57.05) v1(26.43,99.22) v1(26.38,27.65) v1(26.5,71.45) v1(26.55,68.3) v1(26.55,66.7) v1(26.55,65.1) v1(26.55,63.45) v1(26.55,61.88) v1(26.73,46.77) v1(26.73,44.88) v1(26.82,43.5) v1(26.88,41.7) v1(26.93,40.27) v1(27,90.75) v1(27,88.8) v1(27.07,99.25) v1(27.07,74.55) v1(27.18,22.62) v1(27.32,25.35) v1(27.43,98.6) v1(27.38,23.57) v1(27.35,10.2) v1(27.52,94.08) v1(27.57,88.8) v1(27.8,82.15) v1(27.77,74.15) v1(27.9,29.5) v1(27.93,28.43) v1(27.9,27.27) v1(27.93,21.73) v1(27.93,2.83) v1(27.98,24.48) v1(28.07,98.9) v1(28.12,90.72) v1(28.05,30.75) v1(28.12,26.1) v1(28.07,22.52) v1(28.2,92.7) v1(28.25,88.78) v1(28.18,23.4) v1(28.52,70.47) v1(28.5,25.27) v1(28.57,83.47) v1(28.55,71.05) v1(28.7,48.05) v1(28.73,36.83) v1(28.73,26.98) v1(28.77,44.12) v1(28.77,43.52) v1(28.77,42.88) v1(28.77,42.27) v1(28.8,40.98) v1(28.82,35.73) v1(28.8,23.98) v1(28.82,1.25) v1(28.88,88.78) v1(28.88,29.9) v1(28.93,28.35) v1(29,94) v1(28.98,75.67) v1(28.98,31.15) v1(29.15,22.12) v1(29.07,15.2) v1(29.1,7.28) v1(29.2,91.42) v1(29.18,81.85) v1(29.32,73.65) v1(29.35,73.1) v1(29.4,40.95) v1(29.4,40.35) v1(29.4,39.4) v1(29.43,38.2) v1(29.35,33.48) v1(29.4,27.62) v1(29.43,23.3) v1(29.6,90.7) v1(29.6,88.6) v1(29.57,76.83) v1(29.62,75) v1(29.6,67.38) v1(29.65,30.48) v1(29.55,29.07) v1(29.73,93.92) v1(29.73,65.12) v1(29.68,31.65) v1(29.8,66) v1(29.82,49.12) v1(29.88,60.3) v1(29.95,26.93) v1(29.93,3) v1(29.98,23.98) v1(30,22.75) v1(29.98,12.88) v1(30.15,81.65) v1(30.15,76.85) v1(30.15,40.08) v1(30.12,35.1) v1(30.23,88.5) v1(30.18,82.75) v1(30.23,76.17) v1(30.2,74.42) v1(30.25,67.47) v1(30.25,66.7) v1(30.2,38.7) v1(30.18,29.45) v1(30.18,28.18) v1(30.4,90.75) v1(30.35,63.48) v1(30.35,61.98) v1(30.43,22.07) v1(30.52,45.75) v1(30.62,70.47) v1(30.55,7.33) v1(30.8,82.75) v1(30.8,76.2) v1(30.82,75.53) v1(30.8,35.83) v1(30.95,73.12) v1(30.93,32.85) v1(30.95,5.67) v1(30.93,1.4) v1(30.98,33.77) v1(30.98,31.85) v1(30.98,11.62) v1(31.2,21.55) v1(31.32,88.7) v1(31.3,75.1) v1(31.38,75.7) v1(31.35,5.3) v1(31.52,28.12) v1(31.62,54.7) v1(31.65,53.05) v1(31.65,10.07) v1(31.7,23.98) v1(31.7,22.18) v1(31.7,14.62) v1(31.75,34.77) v1(31.77,33.85) v1(31.75,26.93) v1(31.9,92.7) v1(31.85,75.1) v1(31.9,15.18) v1(31.9,14.05) v1(31.88,1.43) v1(32,90.72) v1(32,88.7) v1(32.05,23.15) v1(32.08,98.72) v1(32.15,27.6) v1(32.42,59.77) v1(32.52,94.1) v1(32.48,64.65) v1(32.45,62.92) v1(32.45,61.08) v1(32.5,58.58) v1(32.52,57.52) v1(32.45,55.9) v1(32.52,33.65) v1(32.52,32.75) v1(32.52,28.62) v1(32.6,88.72) v1(32.58,46.8) v1(32.58,31.82) v1(32.62,30.82) v1(32.6,29.6) v1(32.6,22.23) v1(32.6,13.4) v1(32.77,96.75) v1(32.8,26.88) v1(32.88,98.72) v1(33.02,62.12) v1(33.08,63.83) v1(33.08,60.35) v1(33.12,56.88) v1(33.1,24.02) v1(33.2,59.15) v1(33.25,25.02) v1(33.23,23.02) v1(33.27,88.75) v1(33.3,26.25) v1(33.4,30.2) v1(33.4,28.82) v1(33.35,27.68) v1(33.55,47.67) v1(33.58,31.7) v1(33.77,97.12) v1(33.85,22.18) v1(34.02,99.2) v1(34.05,29.38) v1(34.15,90.67) v1(34.15,72.67) v1(34.1,40.58) v1(34.12,32.45) v1(34.1,30.75) v1(34.12,28.23) v1(34.15,26.82) v1(34.15,25.7) v1(34.15,23.18) v1(34.15,8.55) v1(34.12,7.8) v1(34.23,47.15) v1(34.17,24.4) v1(34.3,53.3) v1(34.3,52.7) v1(34.27,52.08) v1(34.27,51.48) v1(34.4,93.78) v1(34.42,70.5) v1(34.4,42.05) v1(34.5,95.95) v1(34.65,88.35) v1(34.58,48.27) v1(34.7,97.12) v1(34.73,10.3) v1(34.85,53.3) v1(34.9,52.7) v1(34.88,39.42) v1(34.95,38.4) v1(35.02,9.12) v1(35.08,49.52) v1(35.23,99.2) v1(35.3,82.3) v1(35.3,81.65) v1(35.33,80.97) v1(35.27,47.3) v1(35.35,94.92) v1(35.35,83.5) v1(35.48,10.32) v1(35.48,9.6) v1(35.65,13.65) v1(35.7,74.67) v1(35.67,42.08) v1(35.77,81.33) v1(35.75,41) v1(35.75,39.52) v1(35.85,90.38) v1(36,82.3) v1(36.05,25) v1(36,23.32) v1(36.08,83.45) v1(36.08,72.22) v1(36.12,12.2) v1(36.08,7.97) v1(36.2,81.75) v1(36.2,24) v1(36.17,14.35) v1(36.33,99.2) v1(36.35,10.18) v1(36.55,25.57) v1(36.55,24.5) v1(36.62,82.4) v1(36.62,15.3) v1(36.65,9.43) v1(36.73,46.88) v1(36.88,90.97) v1(36.9,90.05) v1(36.9,83.47) v1(37.02,91.5) v1(36.95,42.08) v1(37.12,99.2) v1(37.08,93.15) v1(37.17,12.5) v1(37.4,61.5) v1(37.4,59.88) v1(37.45,62.85) v1(37.55,58.45) v1(37.58,9.5) v1(37.8,74.67) v1(37.75,49.2) v1(38.02,99.25) v1(38,42.08) v1(38.02,7.65) v1(38.08,54.6) v1(38.17,15.18) v1(38.25,13.15) v1(38.25,8.2) v1(38.27,13.9) v1(38.3,12.53) v1(38.48,14.65) v1(38.73,95.78) v1(38.67,49.25) v1(38.8,90.42) v1(38.8,42.62) v1(39.33,18.1) v1(39.33,17.5) v1(39.38,88.33) v1(39.48,95.15) v1(39.6,28.07) v1(39.92,18.7) v1(39.92,18.1) v1(40.17,99.15) v1(40.33,27.75) v1(40.42,94.3) v1(40.55,69.95) v1(40.52,69.33) v1(40.45,0.78) v1(40.65,36.1) v1(40.6,19) v1(40.6,18.4) v1(40.75,1.52) v1(40.92,94.3) v1(41.25,39.2) v1(41.17,15.07) v1(41.27,10.6) v1(41.42,99.15) v1(41.38,70.47) v1(41.4,68.25) v1(41.42,37.98) v1(41.35,9.75) v1(41.35,0.9) v1(41.45,34.92) v1(41.58,27.73) v1(41.85,92.6) v1(42.15,32.42) v1(42.52,64.55) v1(42.52,18.1) v1(42.62,97.12) v1(42.62,61.75) v1(42.58,31.65) v1(42.92,70.53) v1(42.88,27.75) v1(42.95,99.12) v1(42.98,72) v1(43,66.75) v1(43.12,18.68) v1(43.25,59.25) v1(43.27,92.72) v1(43.33,0.75) v1(43.38,96.1) v1(43.4,5.67) v1(43.45,97.12) v1(43.6,92.25) v1(43.67,32.95) v1(43.75,69.03) v1(43.75,43.2) v1(43.9,41.67) v1(43.95,91.35) v1(43.95,17.62) v1(44.15,70.45) v1(44.25,27.75) v1(44.35,96.03) v1(44.38,95.15) v1(44.52,34.3) v1(44.52,18.82) v1(44.65,98.55) v1(44.58,91.35) v1(44.58,51.92) v1(44.58,51.33) v1(44.6,50.35) v1(44.6,49.75) v1(44.65,48.55) v1(44.65,47.95) v1(44.7,46.67) v1(44.77,41.7) v1(44.83,20.93) v1(44.92,60.6) v1(44.9,44.38) v1(44.95,58.02) v1(45.02,54.6) v1(44.95,16.57) v1(44.95,5.67) v1(45.08,94.38) v1(45.1,63.38) v1(45.1,17.68) v1(45.25,51.92) v1(45.25,51.33) v1(45.27,49.5) v1(45.27,48.9) v1(45.33,36.1) v1(45.35,69.12) v1(45.4,64.62) v1(45.4,43.25) v1(45.38,41.7) v1(45.42,39.58) v1(45.35,32.8) v1(45.42,21.25) v1(45.52,27.75) v1(45.58,98.55) v1(45.62,14.68) v1(45.7,10.07) v1(45.67,7.53) v1(45.92,94.17) v1(45.85,0.75) v1(45.95,68.58) v1(46.15,34.2) v1(46.38,8.55) v1(46.6,27.73) v1(46.73,56.9) v1(46.83,37.62) v1(46.9,43.27) v1(47.12,42.2) v1(47.08,13.15) v1(47.15,7.45) v1(47.23,20.98) v1(47.2,9.78) v1(47.3,51.95) v1(47.3,49.33) v1(47.27,46.73) v1(47.38,53.75) v1(47.4,44.65) v1(47.38,22) v1(47.38,5.7) v1(47.45,60.55) v1(47.48,54.75) v1(47.62,90.5) v1(47.65,88.42) v1(47.65,58.48) v1(47.67,68.58) v1(47.67,61.75) v1(47.67,14) v1(47.83,67.25) v1(47.75,35.1) v1(48.05,90.95) v1(48,21.95) v1(48.05,20.77) v1(48.15,19.43) v1(48.08,8.57) v1(48.25,18.43) v1(48.52,65.12) v1(48.48,17.75) v1(48.55,5.67) v1(48.58,37.52) v1(48.65,7.42) v1(48.67,68.47) v1(48.83,89.3) v1(48.8,43.3) v1(49,91.12) v1(49.02,16.5) v1(49.05,15.32) v1(49.02,12.97) v1(49.12,0.75) v1(49.33,67.92) v1(49.38,22.77) v1(49.35,8.53) v1(49.55,80.95) v1(49.62,44.23) v1(49.67,83.25) v1(49.67,82.67) v1(49.7,74.22) v1(49.7,51.88) v1(49.67,46.75) v1(49.77,90.42) v1(49.8,35.7) v1(49.92,59.17) v1(49.9,55.6) v1(49.92,22.12) v1(49.88,5.7) v1(50,66.55) v1(50.05,49.25) v1(50.05,13.7) v1(50.05,10.43) v1(50.12,80.65) v1(50.12,65.17) v1(50.12,17.75) v1(50.2,69.1) v1(50.23,7.4) v1(50.3,90.42) v1(50.4,76.92) v1(50.65,80.65) v1(50.9,93.3) v1(50.88,90.42) v1(50.85,39.4) v1(51.05,70.42) v1(50.95,67.7) v1(50.95,34.52) v1(51.02,13.05) v1(51.05,8.53) v1(51.17,80.65) v1(51.17,74.17) v1(51.25,66.58) v1(51.33,33.73) v1(51.33,31.68) v1(51.4,62.2) v1(51.42,22.7) v1(51.45,90.42) v1(51.5,35.77) v1(51.62,83.97) v1(51.65,64.78) v1(51.65,17.38) v1(51.7,80.67) v1(51.67,0.75) v1(51.75,33.1) v1(51.83,7.42) v1(51.85,18.82) v1(52.02,90.42) v1(51.95,51.75) v1(52.02,49.23) v1(52.02,21.93) v1(52.05,5.67) v1(52.1,94.1) v1(52.08,20.45) v1(52.15,11.25) v1(52.2,31.7) v1(52.23,13.65) v1(52.42,83.08) v1(52.38,81.28) v1(52.42,66.6) v1(52.42,53.65) v1(52.4,46.8) v1(52.35,17.75) v1(52.35,10.25) v1(52.55,85.08) v1(52.5,39.3) v1(52.55,35.65) v1(52.55,19.4) v1(52.45,14.62) v1(52.58,90.42) v1(52.62,41.98) v1(52.67,56.92) v1(52.7,31.7) v1(52.83,81.92) v1(52.75,74.17) v1(52.92,8.35) v1(52.95,80.75) v1(52.98,59.33) v1(53,54.62) v1(53.05,16.23) v1(53.02,11.95) v1(53.3,35.83) v1(53.4,69.1) v1(53.5,22.82) v1(53.62,70.4) v1(53.9,33.8) v1(53.88,7.33) v1(54.05,39.5) v1(54.15,31.98) v1(54.2,74.17) v1(54.2,49.23) v1(54.23,41.9) v1(54.2,21.98) v1(54.3,51.85) v1(54.35,17.25) v1(54.38,5.6) v1(54.45,8.53) v1(54.55,0.75) v1(54.77,59.35) v1(54.88,11.68) v1(54.98,96.3) v1(55,69.3) v1(55.05,64.45) v1(55,62.12) v1(55.08,70.38) v1(55.15,7.2) v1(55.4,56.83) v1(55.55,93) v1(55.52,31.95) v1(55.65,46.8) v1(55.7,71.55) v1(55.67,70.53) v1(55.83,17.85) v1(55.85,41.88) v1(55.85,5.6) v1(56.12,92.55) v1(56.12,24.23) v1(56.35,54.45) v1(56.6,18.73) v1(56.83,59.35) v1(56.83,49.1) v1(56.85,23.48) v1(57.14,68.54) v1(57.12,52.08) v1(57.08,11.32) v1(57.17,70.5) v1(57.27,76.65) v1(57.33,54.88) v1(57.4,38) v1(57.52,33.92) v1(57.45,17.9) v1(57.6,74.78) v1(57.85,62.6) v1(57.88,41.75) v1(57.88,19.27) v1(57.88,0.75) v1(57.98,22.4) v1(58.27,57.15) v1(58.4,81.9) v1(58.38,20.52) v1(58.52,80.7) v1(58.45,49.4) v1(58.48,11.97) v1(58.58,88.9) v1(58.65,21.77) v1(58.7,47.3) v1(58.7,10.72) v1(58.75,81.25) v1(58.8,58.02) v1(58.9,34.02) v1(58.95,81.88) v1(58.98,74.17) v1(58.95,66.42) v1(59.02,54.3) v1(59.05,51.62) v1(59.15,63.85) v1(59.1,62.23) v1(59.12,60.48) v1(59.08,9.15) v1(59.23,88.5) v1(59.17,84.03) v1(59.23,1.6) v1(59.3,81.22) v1(59.3,18.12) v1(59.4,53) v1(59.48,50.38) v1(59.67,15.3) v1(59.73,14.05) v1(59.7,12.07) v1(59.73,9.82) v1(59.67,7.62) v1(59.88,0.75) v1(60.05,20.27) v1(60.33,64.55) v1(60.48,17.18) v1(60.62,77.4) v1(60.58,57.88) v1(60.6,19.45) v1(60.83,62.77) v1(60.77,59.42) v1(60.75,1.8) v1(60.9,74.17) v1(60.92,67.33) v1(61,48.33) v1(61.02,11.6) v1(60.98,9.95) v1(61.1,61.12) v1(61.25,41.67) v1(61.42,63.67) v1(61.55,75.17) v1(61.52,12.97) v1(61.45,7.67) v1(61.65,67.35) v1(61.6,65.12) v1(61.73,53.95) v1(61.7,27.77) v1(61.73,9.05) v1(61.8,52.25) v1(61.8,10.93) v1(61.85,60.3) v1(61.9,42.75) v1(62.08,31.25) v1(62.25,58.65) v1(62.35,91.17) v1(62.35,65.25) v1(62.58,67.33) v1(62.83,16.98) v1(62.85,27.82) v1(62.85,18.02) v1(63,88.55) v1(63.05,86.12) v1(63,85.55) v1(63.02,84.95) v1(63.15,82) v1(63.1,42.75) v1(63.23,50.58) v1(63.27,82.6) v1(63.27,61.88) v1(63.27,37.62) v1(63.3,0.82) v1(63.55,58.67) v1(63.52,25.02) v1(63.48,18.05) v1(63.62,60.05) v1(63.62,31.88) v1(63.7,82) v1(63.83,82.6) v1(63.92,96.58) v1(63.88,37.38) v1(64.05,27.8) v1(64.15,64.25) v1(64.15,12.75) v1(64.15,11.75) v1(64.15,10.78) v1(64.15,9.78) v1(64.15,7.78) v1(64.35,45.02) v1(64.38,82.7) v1(64.5,67.47) v1(64.47,37.7) v1(64.6,22.48) v1(64.72,1) v1(64.83,88) v1(64.88,88.55) v1(64.95,68.05) v1(64.97,59.52) v1(65.25,22.62) v1(65.28,2.35) v1(65.4,68.65) v1(65.38,25.05) v1(65.4,24.27) v1(65.38,14.47) v1(65.53,65.33) v1(65.55,63.45) v1(65.45,44.75) v1(65.55,39.5) v1(65.47,13.57) v1(65.58,45.92) v1(65.72,74.2) v1(65.67,0.9) v1(65.92,53.85) v1(66.03,17.95) v1(66.15,2.35) v1(66.3,24.9) v1(66.38,24.32) v1(66.42,14.47) v1(66.55,70.85) v1(66.45,65.12) v1(66.53,45.9) v1(66.5,39.48) v1(66.47,28.62) v1(66.45,13.53) v1(66.6,92.17) v1(66.58,85) v1(66.88,75.25) v1(66.9,60.23) v1(67.12,71.12) v1(67.15,89.3) v1(67.28,53.83) v1(67.38,59.02) v1(67.38,39.55) v1(67.38,28.62) v1(67.55,86.8) v1(67.5,62.65) v1(67.5,55.48) v1(67.62,89.58) v1(67.9,85.78) v1(68.12,93.95) v1(68.35,93.3) v1(68.3,31.25) v1(68.33,14.6) v1(68.35,13.55) v1(68.5,7.58) v1(68.65,28.6) v1(68.83,2.3) v1(68.83,0.75) v1(68.88,9.1) v1(69.08,90.25) v1(69.25,65.55) v1(69.17,61.2) v1(69.22,60.4) v1(69.25,32.73) v1(69.2,15.93) v1(69.47,71.78) v1(69.5,64.92) v1(69.47,16.5) v1(69.45,7.55) v1(69.67,59.1) v1(69.8,98.97) v1(69.92,56.55) v1(69.92,27.8) v1(70.25,28.6) v1(70.4,72.78) v1(70.6,60.02) v1(70.7,13.95) v1(70.9,79.85) v1(70.92,7.67) v1(71.05,62.77) v1(71.05,28.62) v1(71.05,16.57) v1(71.3,10.7) v1(71.28,9.07) v1(71.3,0.82) v1(71.38,12.18) v1(71.62,86.65) v1(71.67,98.97) v1(71.78,13.35) v1(72,80.5) v1(71.95,7.72) v1(72.08,28.62) v1(72.2,61.52) v1(72.17,16.02) v1(72.28,96.35) v1(72.3,55.25) v1(72.5,86.53) v1(72.65,12.9) v1(72.88,13.7) v1(72.88,7.5) v1(73.03,85.72) v1(73.2,34.8) v1(73.25,16.57) v1(73.33,96.35) v1(73.3,72.2) v1(73.38,24.65) v1(73.45,98.95) v1(73.45,54.88) v1(73.6,86.3) v1(73.65,0.8) v1(73.75,26.6) v1(73.95,24.65) v1(74.2,86.28) v1(74.3,50.12) v1(74.28,25.55) v1(74.33,15.95) v1(74.35,12.85) v1(74.35,7.6) v1(74.42,13.95) v1(74.5,55.98) v1(74.55,24.93) v1(74.53,16.6) v1(74.58,80.53) v1(74.67,73.58) v1(74.72,71.55) v1(74.72,57.02) v1(74.65,30.3) v1(75.05,97.3) v1(75.1,83.58) v1(75.35,98.97) v1(75.47,83.92) v1(75.62,88.8) v1(75.62,88.05) v1(75.58,0.75) v1(75.72,91.5) v1(75.72,90.95) v1(75.72,60.88) v1(75.95,50.2) v1(76.05,42.48) v1(76.17,55.23) v1(76.2,20.25) v1(76.25,13.9) v1(76.25,10.57) v1(76.25,9.03) v1(76.33,80.5) v1(76.33,16.38) v1(76.28,12.25) v1(76.42,15.28) v1(76.88,7.75) v1(77.12,39.83) v1(77.17,40.5) v1(77.38,9.6) v1(77.75,79.47) v1(77.78,40.55) v1(77.88,61.55) v1(78.22,97.65) v1(78.33,7.4) v1(78.53,30.07) v1(78.67,62.77) v1(78.67,59.48) v1(78.95,41.55) v1(79.05,13.25) v1(79.1,80.75) v1(79.1,30.75) v1(79.08,12.5) v1(79.12,8.85) v1(79.22,79.45) v1(79.45,93.6) v1(79.53,30.1) v1(79.65,91.05) v1(79.67,31.3) v1(79.85,70.1) v1(80.12,31.85) v1(80.2,0.95) v1(80.33,60.8) v1(80.35,59.62) v1(80.55,70.7) v1(80.45,30.88) v1(80.5,30.07) v1(80.58,93.83) v1(80.65,82.15) v1(80.78,32.48) v1(80.9,96.17) v1(80.97,50.23) v1(81.12,2.25) v1(81.17,63.95) v1(81.62,91.05) v1(81.58,30.3) v1(81.72,95.55) v1(82.05,70.35) v1(82.03,4.6) v1(82.22,26.15) v1(82.2,13.95) v1(82.25,11.95) v1(82.2,9.03) v1(82.55,64.08) v1(82.5,60.65) v1(82.55,55.85) v1(82.58,98.5) v1(82.6,57.15) v1(82.65,6.35) v1(82.78,50.17) v1(82.88,61.65) v1(83.1,56.58) v1(83.08,31.52) v1(83.17,62.6) v1(83.33,93.33) v1(83.28,91.1) v1(83.3,87.97) v1(83.3,46.05) v1(83.47,4.67) v1(83.62,94.17) v1(83.62,58.7) v1(83.6,2.23) v1(83.65,90.53) v1(83.7,82.35) v1(83.85,50.95) v1(84.03,87.17) v1(84.1,96.05) v1(84.22,37.73) v1(84.25,13.72) v1(84.28,93.35) v1(84.42,59.42) v1(84.38,6.3) v1(84.47,94.15) v1(84.55,61.35) v1(84.5,4.6) v1(84.58,62.25) v1(84.67,62.88) v1(84.72,29.02) v1(84.83,60.38) v1(84.83,25.2) v1(84.95,52) v1(85.22,93.35) v1(85.2,16.02) v1(85.35,46.05) v1(85.42,18.5) v1(85.42,10.47) v1(85.58,62.5) v1(85.72,33.73) v1(85.72,29.05) v1(85.7,14.03) v1(85.8,48.38) v1(85.75,32.73) v1(85.92,53.17) v1(85.95,99.25) v1(85.95,2.25) v1(86.15,92.22) v1(86.3,9.6) v1(86.35,6.33) v1(86.38,67.6) v1(86.55,46.05) v1(86.47,4.67) v1(86.83,49.48) v1(87.03,54.58) v1(87.03,34.27) v1(87,32.25) v1(87,20.93) v1(86.95,18.48) v1(87.22,44.7) v1(87.25,26.07) v1(87.25,10.25) v1(87.25,7.85) v1(87.28,99.25) v1(87.28,62.77) v1(87.33,13.55) v1(87.42,64.17) v1(87.42,11.85) v1(87.47,61.45) v1(87.78,9.35) v1(88.03,69.75) v1(88.05,67.67) v1(88.05,30.43) v1(88.05,2.23) v1(88.1,33.7) v1(88.12,32.5) v1(88.22,55.05) v1(88.2,45.38) v1(88.35,21.68) v1(88.33,6.38) v1(88.38,16.55) v1(88.67,50.25) v1(88.83,51.9) v1(88.83,45.95) v1(88.8,8) v1(88.88,99.25) v1(89,86.25) v1(89.08,10.3) v1(89.15,66.6) v1(89.28,20.57) v1(89.4,64) v1(89.55,71.17) v1(89.55,57.1) v1(89.7,81.85) v1(89.83,19.23) v1(89.8,16.27) v1(89.95,4.62) v1(90.05,2.27) v1(90.08,9.15) v1(90.2,92.12) v1(90.25,67.33) v1(90.28,73.38) v1(90.28,13.93) v1(90.42,17.98) v1(90.53,31.8) v1(90.53,29.6) v1(90.58,99.25) v1(90.65,85.75) v1(90.85,96.75) v1(90.75,72.5) v1(90.85,20.05) v1(90.9,22.85) v1(91.1,34.73) v1(91.12,10.22) v1(91.33,65.65) v1(91.33,57.17) v1(91.33,55.98) v1(91.3,13.97) v1(91.42,6.97) v1(91.55,19.15) v1(91.6,86.67) v1(91.85,87.67) v1(91.85,23.73) v1(91.85,17.12) v1(91.9,57.83) v1(92.1,99.25) v1(92.12,29.57) v1(92.2,34.2) v1(92.35,33.05) v1(92.38,4.58) v1(92.5,96.53) v1(92.5,95.5) v1(92.5,2.23) v1(92.62,57.15) v1(92.72,39.4) v1(92.72,16.5) v1(92.67,14.12) v1(92.85,26.05) v1(92.85,22.7) v1(93.03,7.22) v1(93.17,87.88) v1(93.25,8.5) v1(93.28,32.17) v1(93.5,86.47) v1(93.53,83.38) v1(93.55,81.22) v1(93.55,19.07) v1(93.58,84.95) v1(93.7,28.85) v1(93.75,39.73) v1(93.75,16.6) v1(93.8,13.97) v1(93.9,92.12) v1(93.92,82.17) v1(94,69.28) v1(93.95,57.23) v1(94,26.02) v1(94.2,49.17) v1(94.22,9.85) v1(94.35,18.05) v1(94.3,4.65) v1(94.4,86.6) v1(94.4,80.47) v1(94.55,90.7) v1(94.45,39.95) v1(94.53,22.65) v1(94.6,52.55) v1(94.67,20.2) v1(94.7,2.2) v1(94.75,99.22) v1(94.75,93.72) v1(94.8,75.42) v1(94.8,29.62) v1(94.75,16.25) v1(94.75,7.65) v1(95,26.1) v1(95.05,23.75) v1(95,13.68) v1(95.1,57.33) v1(95.2,34.08) v1(95.4,89.78) v1(95.62,52.62) v1(95.6,19.05) v1(95.85,22.68) v1(96.05,24.52) v1(96.25,94) v1(96.17,28.88) v1(96.25,4.6) v1(96.38,90.6) v1(96.4,6.38) v1(96.45,81.3) v1(96.55,56.4) v1(96.5,2.23) v1(96.67,20.15) v1(96.85,96.72) v1(96.78,95.55) v1(96.75,91.08) v1(96.83,34.15) v1(96.85,32.33) v1(96.88,99.25) v1(96.88,78.42) v1(96.9,77.1) v1(96.9,75.42) v1(96.88,28.85) v1(97,79.3) v1(97,45.17) v1(97.08,82.1) v1(97.08,56.38) v1(97.1,18) v1(97.25,67.5) v1(97.15,11.9) v1(97.35,22.68) v1(97.38,86.6) v1(97.38,63.17) v1(97.42,57.77) v1(97.55,62.3) v1(97.55,61.42) v1(97.55,19.25) v1(97.6,92.12) v1(97.58,24.18) v1(97.78,12) v1(97.9,57.5) v1(97.9,7.22) v1(97.95,49.1) v1(98.15,79.38) v1(98.17,78.28) v1(98.2,76.85) v1(98.15,68.88) v1(98.28,86.9) v1(98.3,83.6) v1(98.33,75.35) v1(98.3,61.25) v1(98.28,59.2) v1(98.4,89) v1(98.53,80.65) v1(98.55,13.75) v1(98.8,58.05) v1(98.83,18.82) v1(98.92,90.83) v1(99.1,93.85) v1(99.1,30.52) v1(99.25,28.85) v1(99.22,16.75) v1(99.17,6.97) v1(99.35,98.8) v1(99.53,97.22) v1(99.5,95.83) v1(99.45,11.68) v1(99.5,4.62) v1(99.6,86.78) v1(99.6,83.6) v1(99.6,12.55) v1(99.7,49.1) v1(99.65,26.07) v1(99.83,76.95) v1(99.78,75.42) v1(99.88,90.65) v1(100,71.38) v1(99.95,20.43) v1(100.08,63.4) v1(100.1,28.82) v1(100.22,65.25) v1(100.33,79.3) v1(100.28,15.95) v1(100.55,81.92) v1(100.58,59.42) v1(100.62,17.4) v1(100.67,84.55) v1(100.7,71.38) v1(100.65,30.48) v1(101,75.38) v1(100.95,40.15) v1(101.15,52.23) v1(101.22,21.7) v1(101.15,18.43) v1(101.28,98.85) v1(101.42,95.88) v1(101.45,97.28) v1(101.58,80.2) v1(101.7,75.38) v1(101.92,86.53) v1(101.97,76.62) v1(102.03,30.45) v1(101.95,10.18) v1(102.25,40.65) v1(102.2,13.38) v1(102.35,59.95) v1(102.3,32.33) v1(102.38,85.22) v1(102.4,78.1) v1(102.42,20.65) v1(102.47,40.15) v1(102.53,28.85) v1(102.78,65.4) v1(102.85,64.12) v1(102.8,62.83) v1(102.78,38.15) v1(102.85,16.95) v1(102.88,22.45) v1(103.12,79.8) v1(103.08,44.17) v1(103.15,75.53) v1(103.25,19.75) v1(103.33,86.45) v1(103.42,89.1) v1(103.38,84.12) v1(103.45,98.9) v1(103.47,39.3) v1(103.62,97.33) v1(103.6,95.92) v1(103.62,82.1) v1(103.65,11.25) v1(103.9,48.88) v1(103.9,32.15) v1(103.9,16.38) v1(103.95,65.2) v1(103.95,63.88) v1(104.03,44.15) v1(104.03,42.5) v1(104.17,60.08) v1(104.25,13.88) v1(104.2,8.82) v1(104.17,4.1) v1(104.3,62.05) v1(104.3,22.77) v1(104.3,22.12) v1(104.3,21.5) v1(104.42,94.38) v1(104.53,51.88) v1(104.6,92.8) v1(104.58,91.4) v1(104.6,11.35) v1(104.7,15.07) v1(104.83,28.9) v1(104.9,64.25) v1(104.95,66.08) v1(105,63.33) v1(105.05,37.15) v1(104.97,7.12) v1(105.08,39.05) v1(105.15,89.95) v1(105.15,30.48) v1(105.15,4.55) v1(105.3,75.45) v1(105.33,45.12) v1(105.33,44.17) v1(105.33,42.5) v1(105.53,21.1) v1(105.62,94.08) v1(105.7,98.8) v1(105.65,60.98) v1(105.65,32.12) v1(105.85,95.83) v1(105.8,92.5) v1(105.78,91.1) v1(105.83,88.95) v1(105.75,65.88) v1(105.85,59.95) v1(105.88,97.22) v1(105.88,71.28) v1(105.9,4.35) v1(106.03,66.72) v1(106,13.65) v1(106,13.07) v1(106.25,64.12) v1(106.2,11.32) v1(106.28,44.2) v1(106.47,52.62) v1(106.45,38.9) v1(106.45,19.35) v1(106.45,6.78) v1(106.58,71.28) v1(106.9,89.9) v1(107,61.52) v1(107.12,41) v1(107.28,75.72) v1(107.28,66.83) v1(107.28,62.8) v1(107.35,29.85) v1(107.5,64.1) v1(107.65,76.58) v1(107.65,60.95) v1(107.72,38.98) v1(107.72,26.2) v1(107.78,5.22) v1(107.88,89.1) v1(108.05,66.9) v1(108.03,25.68) v1(108.05,11.3) v1(108.12,82.25) v1(108.12,46.5) v1(108.08,43.85) v1(108.08,19.48) v1(108.25,66.25) v1(108.15,16.2) v1(108.15,15.15) v1(108.28,42.5) v1(108.35,38.88) v1(108.28,36.35) v1(108.4,98.8) v1(108.55,95.83) v1(108.47,89.88) v1(108.53,47.08) v1(108.5,32.27) v1(108.53,26.2) v1(108.58,97.22) v1(108.6,13.05) v1(108.67,44.17) v1(108.65,22.88) v1(108.7,6.75) v1(108.88,66.88) v1(108.92,65.3) v1(108.92,62.67) v1(108.92,53.05) v1(108.95,60.92) v1(108.95,44.73) v1(109.25,75.22) v1(109.5,12.18) v1(109.6,36.9) v1(109.7,90.05) v1(109.72,84.2) v1(109.72,50.27) v1(109.65,32.08) v1(109.8,16.4) v1(109.85,4.72) v1(109.88,88.35) v1(109.88,79.83) v1(109.95,94.3) v1(109.97,38.9) v1(109.95,11.32) v1(109.95,7.22) v1(110.08,85.67) v1(110.1,49.5) v1(110.25,30.12) v1(110.42,18.93) v1(110.42,15.4) v1(110.6,47) v1(110.72,93.47) v1(110.72,11.32) v1(110.83,91.72) v1(110.78,82.55) v1(110.78,14.05) v1(110.92,84.42) v1(110.9,80.92) v1(111,40.45) v1(110.97,6.72) v1(111.1,25.7) v1(111.35,89.33) v1(111.4,88.35) v1(111.55,47.58) v1(111.58,37.62) v1(111.58,29.73) v1(111.72,77.45) v1(111.67,40.38) v1(111.75,44.58) v1(111.75,26.75) v1(111.9,12.8) v1(111.9,7.03) v1(111.92,4.62) v1(112,57) v1(112.1,84.22) v1(112.08,57.7) v1(112.22,85.5) v1(112.17,81.2) v1(112.17,34.42) v1(112.2,24.05) v1(112.25,18.98) v1(112.22,16.35) v1(112.3,93.65) v1(112.28,36.23) v1(112.28,32.92) v1(112.42,78.28) v1(112.38,46.6) v1(112.42,40.42) v1(112.53,74.17) v1(112.47,9.18) v1(112.7,90.55) v1(112.78,92.15) v1(112.8,88.38) v1(112.83,44.3) v1(112.8,43.65) v1(112.8,42.98) v1(112.88,67.08) v1(112.9,61.48) v1(112.9,37.6) v1(112.88,8.22) v1(112.97,89.33) v1(112.95,62.98) v1(113.05,19) v1(113,11.18) v1(113.1,86.25) v1(113.12,75.47) v1(113.08,59.77) v1(113.12,57.3) v1(113.2,12.45) v1(113.3,40.33) v1(113.42,82.58) v1(113.47,84.33) v1(113.62,77.38) v1(113.7,93.62) v1(113.72,73.92) v1(113.7,34.08) v1(113.72,28.45) v1(113.78,13.5) v1(113.78,10.5) v1(113.88,71.88) v1(113.97,52.25) v1(113.97,32.08) v1(114.2,95) v1(114.22,89.92) v1(114.3,16.43) v1(114.42,98.97) v1(114.55,66.03) v1(114.7,92.2) v1(114.65,11.57) v1(115.05,51.3) v1(114.97,18.3) v1(115.12,57.88) v1(115.17,73.85) v1(115.38,12.6) v1(115.62,91.47) v1(115.62,87.38) v1(115.62,86.55) v1(115.62,83.35) v1(115.62,76.15) v1(115.6,71.83) v1(115.67,70.08) v1(115.7,58.7) v1(115.85,67.92) v1(115.78,63.45) v1(115.97,30.82) v1(116.1,17.12) v1(116.28,92.38) v1(116.55,50.77) v1(116.47,20.93) v1(116.62,66.38) v1(116.67,57.9) v1(116.72,43.35) v1(116.65,2.85) v1(116.75,26.85) v1(116.92,37.77) v1(117.05,41.33) v1(117,39.08) v1(117.12,85.92) v1(117.1,40.23) v1(117.17,89.9) v1(117.22,83.92) v1(117.17,81.85) v1(117.25,55.15) v1(117.28,77.95) v1(117.28,73.92) v1(117.35,15.93) v1(117.28,3.52) v1(117.42,87.92) v1(117.38,53.83) v1(117.4,12.72) v1(117.4,6.12) v1(117.45,37.25) v1(117.53,34.12) v1(117.5,31.4) v1(117.53,20.57) v1(117.53,14.32) v1(117.67,92.35) v1(117.9,71.15) v1(117.92,67.25) v1(118.05,77.35) v1(118.05,75.78) v1(118.05,73.42) v1(118.12,82.75) v1(118.1,78.6) v1(118.17,84.83) v1(118.15,81.08) v1(118.3,28.05) v1(118.67,93.83) v1(118.67,1.8) v1(118.78,90.92) v1(118.8,86.67) v1(118.78,19.02) v1(118.92,87.95) v1(118.95,89.35) v1(119.05,28.98) v1(118.97,27.07) v1(118.95,25.73) v1(118.95,20.98) v1(119.25,86.25) v1(119.25,84.35) v1(119.25,82.5) v1(119.25,80.58) v1(119.25,79.33) v1(119.25,77.42) v1(119.25,75.58) v1(119.25,73.65) v1(119.25,71.78) v1(119.25,69.88) v1(119.25,68.03) v1(119.25,66.1) v1(119.25,64.97) v1(119.25,63.08) v1(119.25,61.23) v1(119.25,59.3) v1(119.25,56.3) v1(119.22,52.45) v1(119.25,51.05) v1(119.25,47.25) v1(119.25,44.05) v1(119.25,42.15) v1(119.25,40.3) v1(119.25,38.38) v1(119.25,36.85) v1(119.25,34.95) v1(119.25,33.1) v1(119.25,31.18)
